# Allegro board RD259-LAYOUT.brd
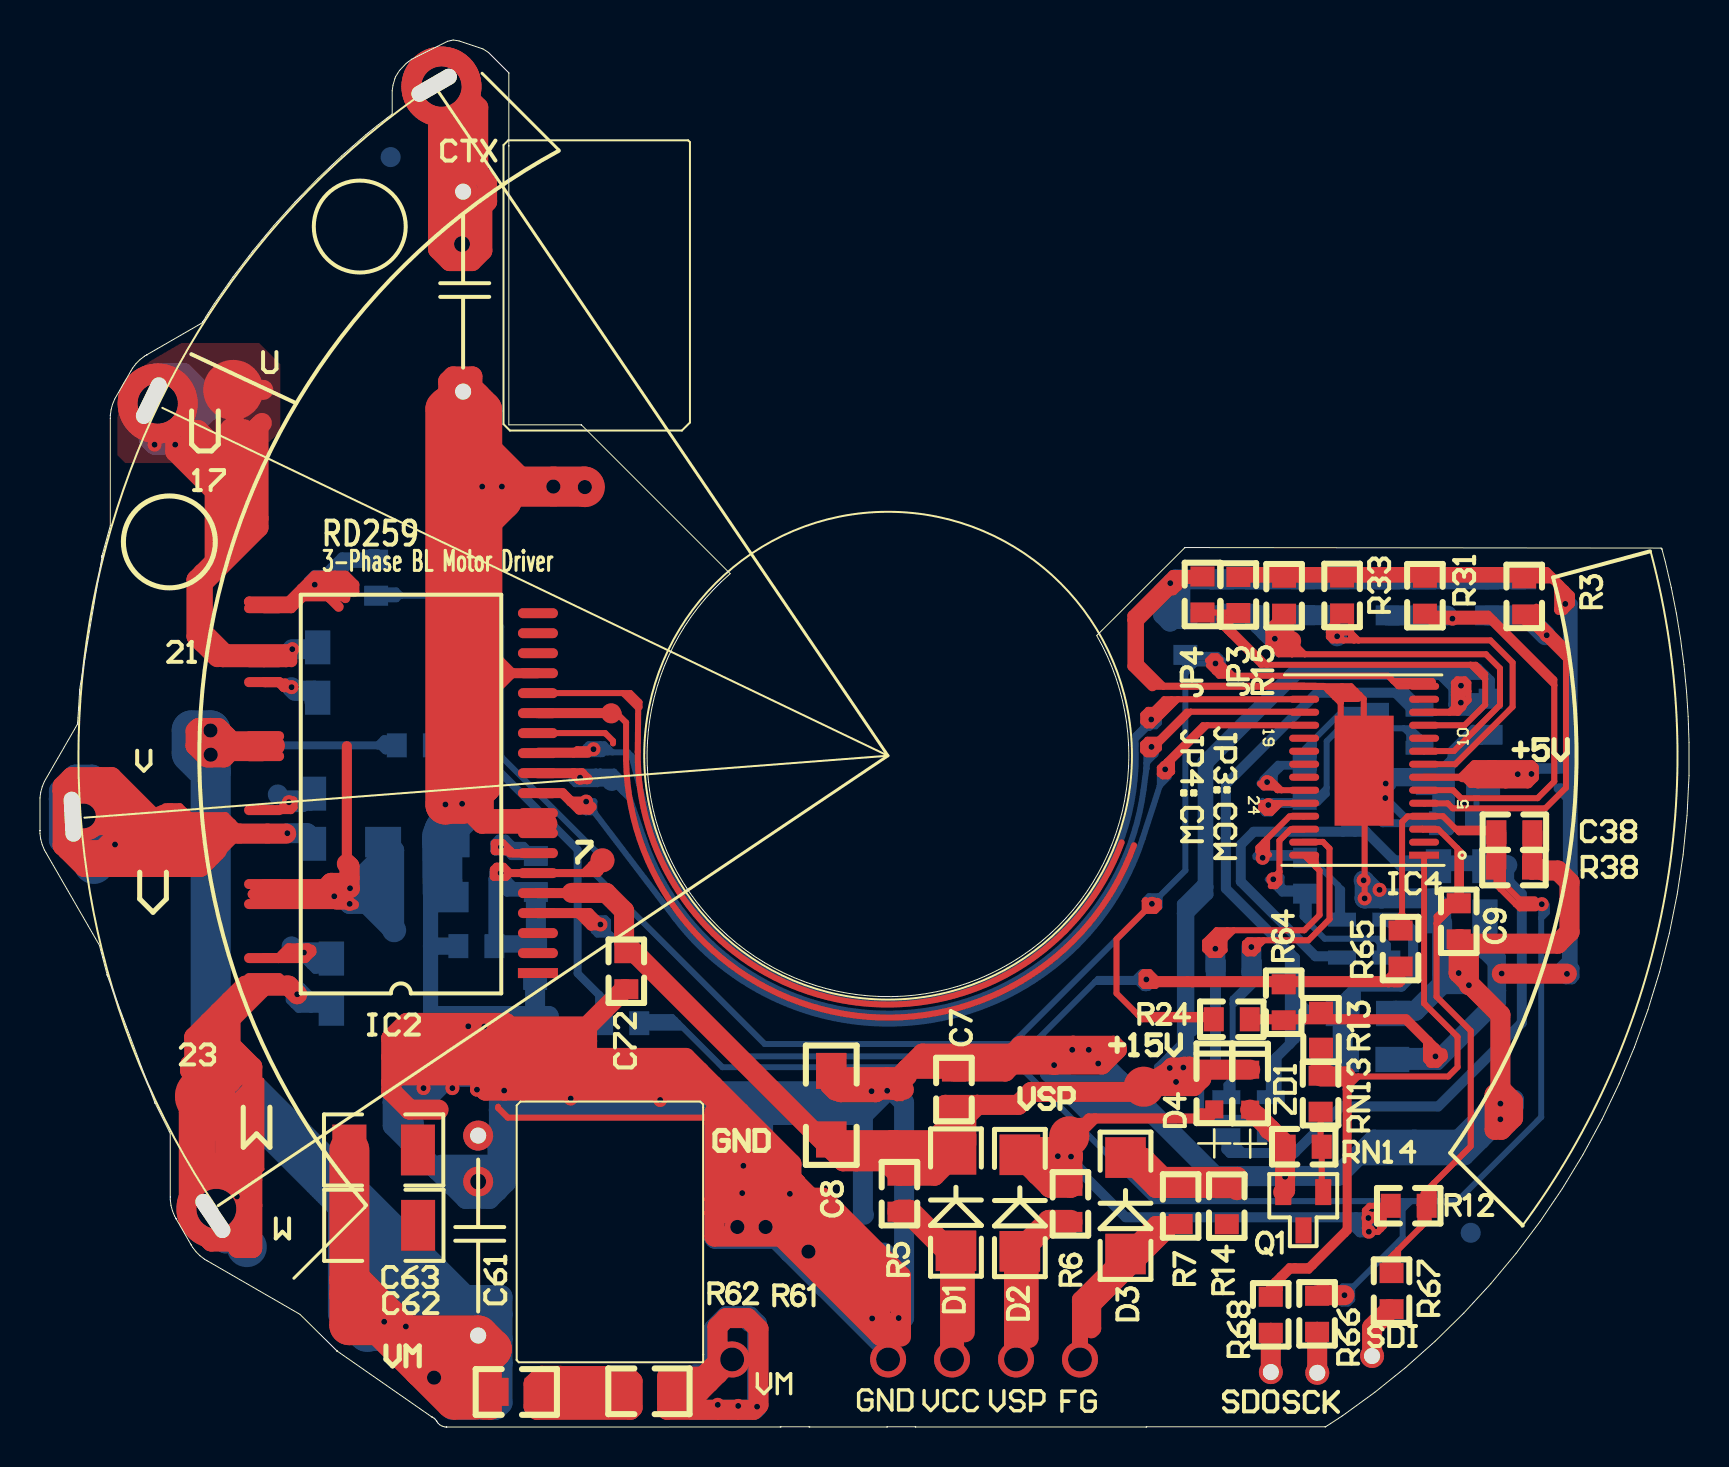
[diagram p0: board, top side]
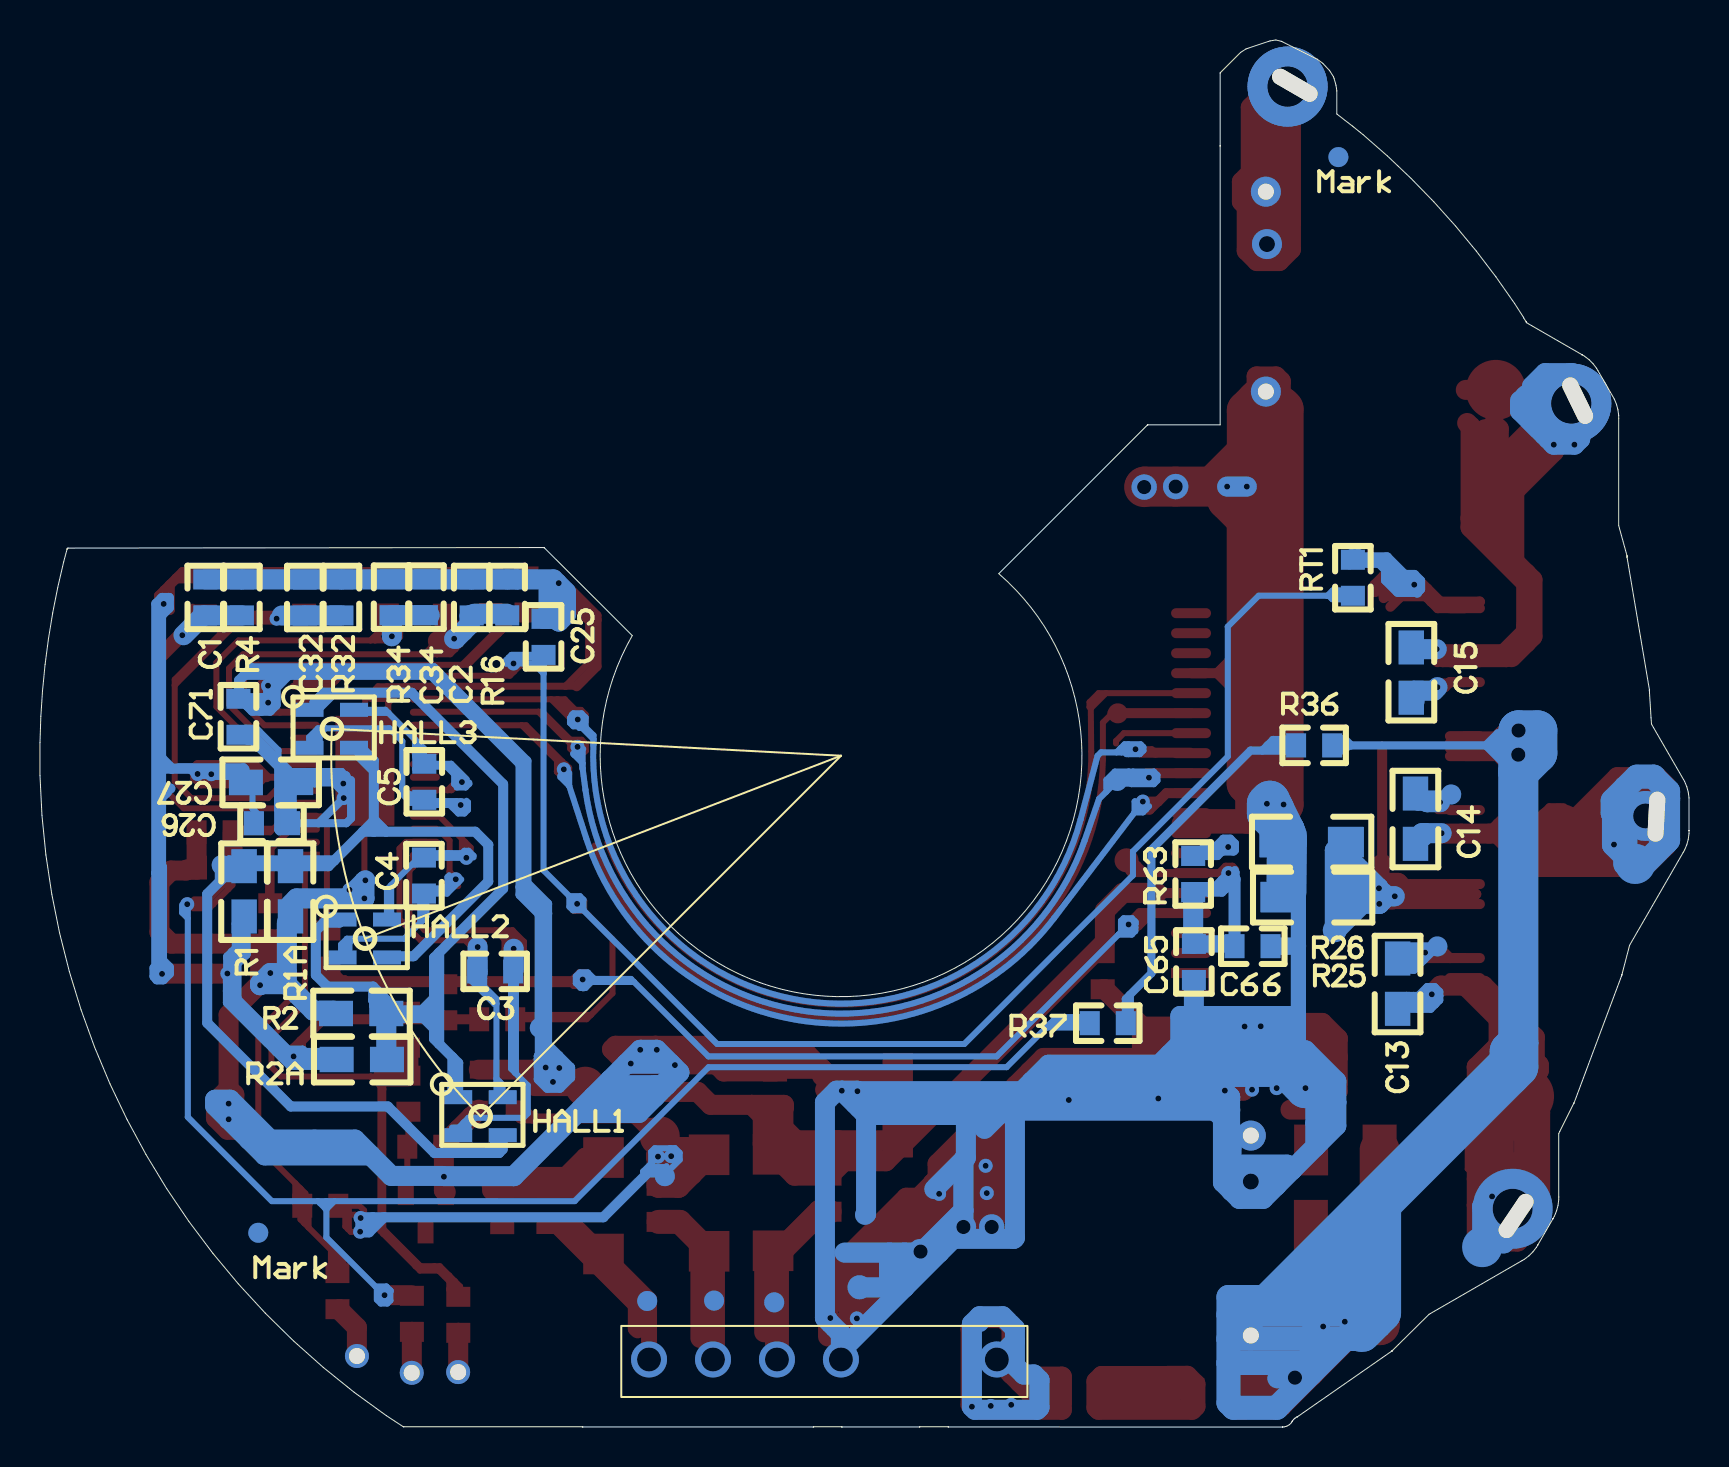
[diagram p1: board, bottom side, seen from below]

Outline 82.5 x 69.38 mm; copper layers: TOP, BOTTOM. Coordinates in mm from the lower left corner of the outline.
Outline path: 0,29.83 0,29.83 0,31.47 0.04,31.75 0.11,32.03 0.22,32.29 1.88,35.16 1.9,35.48 1.98,36.84 1.98,36.85 1.98,36.86 1.98,36.87 3.1,43.5 3.1,43.52 3.1,43.53 3.1,43.54 3.1,43.56 3.1,43.58 3.1,43.58 3.52,45.09 3.52,50.45 3.52,50.6 3.56,50.88 3.63,51.15 3.74,51.42 4.56,52.84 4.63,52.96 4.8,53.19 5,53.39 5.22,53.56 5.34,53.63 5.35,53.64 8.11,55.23 8.14,55.27 8.14,55.28 8.15,55.29 8.27,55.48 8.28,55.49 8.28,55.5 8.28,55.51 8.73,56.2 9.66,57.53 10.65,58.82 11.68,60.08 12.77,61.29 13.9,62.45 15.08,63.57 16.31,64.64 16.83,65.07 17.62,65.68 17.62,66.84 17.66,67.11 17.75,67.44 17.78,67.53 17.99,67.85 18.32,68.21 18.6,68.42 20.39,69.31 20.67,69.38 20.96,69.33 22.16,68.93 22.44,68.75 23.44,67.75 23.44,67.74 23.45,67.74 23.45,67.73 23.46,67.72 23.46,64.08 23.46,64.08 23.46,50.13 27.07,50.13 27.08,50.13 27.09,50.12 27.1,50.11 34.53,42.68 arc(40.41,21.7) 52.87,39.59 57.27,43.98 57.27,43.98 57.28,43.99 57.29,43.99 81.09,43.96 81.1,43.96 81.12,43.95 81.13,43.94 81.13,43.93 81.14,43.91 81.14,43.91 81.31,43.27 81.61,42 81.86,40.72 82.07,39.43 82.24,38.14 82.37,36.84 82.45,35.53 82.5,34.23 82.5,32.58 82.4,30.6 82.2,28.62 81.91,26.65 81.51,24.7 81.03,22.77 80.44,20.87 79.77,19 79,17.17 78.14,15.37 77.19,13.63 76.16,11.93 75.04,10.28 73.85,8.69 72.57,7.16 71.23,5.7 69.81,4.3 68.32,2.98 66.78,1.74 65.17,0.57 64.33,0.02 64.32,0.02 64.31,0.01 64.3,0.01 64.29,0.01 55.37,0.01 55.36,0 55.35,0 55.34,0 43.82,0 43.81,0 43.8,0.01 43.78,0.01 42.4,0.01 42.38,0 42.37,0 42.36,0 38.51,0 38.5,0 38.49,0 38.47,0.01 37.07,0.01 37.06,0 37.05,0 37.04,0 20.34,0 20.33,0 20.26,0 20.12,0.04 20,0.11 19.89,0.21 19.85,0.28 19.85,0.3 19.82,0.33 19.77,0.39 19.71,0.44 19.64,0.49 19.61,0.51 19.6,0.51 19.58,0.52 14.87,3.79 14.85,3.81 14.84,3.82 14.83,3.83 13,5.64 8.36,8.32 8.23,8.39 8.01,8.56 7.81,8.76 7.63,8.99 7.56,9.11 7.56,9.12 6.81,10.42 6.8,10.43 6.73,10.55 6.63,10.81 6.55,11.08 6.52,11.36 6.52,11.51 6.52,14.67 6.47,14.78 5.76,16.19 5.76,16.2 5.75,16.22 3.39,22.54 3.38,22.55 3.37,22.57 3.36,22.6 3.36,22.62 3.36,22.63 2.97,24.09 0.29,28.74 0.22,28.86 0.11,29.13 0.04,29.4 0,29.68 0,29.83

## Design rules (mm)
constraint set DEFAULT: 

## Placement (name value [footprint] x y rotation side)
C1  -  [0603_1]  74.23 42.4 270 bottom
C2  -  [0603_1]  60.9 42.4 270 bottom
C3  -  [0603_1]  60.63 22.79 180 bottom
C4  -  [0603_1]  63.29 28.48 270 bottom
C5  -  [0603_1]  63.27 33.17 270 bottom
C7  -  [0603_1]  45.72 15.98 90 top
C8  -  [1206_1]  39.83 14.39 90 top
C9  -  [0603_1]  70.98 26.2 270 top
C13  -  [0805_1]  14.58 20.92 90 bottom
C14  -  [0805_1]  13.68 29.17 90 bottom
C15  -  [0805_1]  13.89 38.99 270 bottom
C25  -  [0603_1]  57.3 40.42 270 bottom
C26  -  [0603_1]  71.79 30.2 180 bottom
C27  -  [0805_1]  72.19 32.24 180 bottom
C32  -  [0603_1]  69.25 42.39 270 bottom
C34  -  [0603_1]  63.19 42.41 270 bottom
C38  -  [0603_1]  74.66 29.75 180 top
C61  -  [C_CBB]  21.92 4.58 90 top
C62  -  [1210]  15.49 10.09 0 top
C63  -  [1210]  15.48 13.86 0 top
C65  -  [0603_1]  24.77 24.16 270 bottom
C66  -  [0603_1]  22.74 24.05 180 bottom
C71  -  [0603_1]  72.57 36.43 270 bottom
C72  -  [0603_1]  29.33 23.7 270 top
CTX  -  [C_CBB]  21.17 51.79 90 top
D1  -  [RS1M_SMD]  45.81 8.8 90 top
D2  -  [RS1M_SMD]  49.01 8.78 90 top
D3  -  [RS1M_SMD]  54.3 8.64 90 top
D4  -  [D0603]  58.75 15.89 90 top
HALL1  -  [HW101_A]  60.19 15.69 180 bottom
HALL2  -  [HW101_A]  65.97 24.57 180 bottom
HALL3  -  [HW101_A]  67.63 35.06 180 bottom
IC2  -  [SSOP30_TPD4204F]  24.91 22.71 180 top
IC4  -  [TC78B043FNG]  69.24 28.6 180 top
JP3  -  [0603_1]  59.95 42.52 270 top
JP4  -  [0603_1]  58.16 42.54 270 top
NOREF  -  []  6.49 44.22 0 top
NOREF#2  -  []  15.92 60.08 0 top
NOREF#3  -  []  77.04 19.24 0 top
NOREF#4  -  []  57.93 3.08 0 top
NOREF#5  -  []  28.52 9.23 90 top
NOREF#6  -  []  79.56 38.47 0 top
Q1  -  [SOT23_NPN]  63.08 9.79 180 top
R1  -  [0805_1]  72.28 25.54 90 bottom
R1A  -  [0805_1]  69.96 25.54 90 bottom
R2  -  [0805_1]  65.17 20.69 0 bottom
R2A  -  [0805_1]  65.14 18.38 0 bottom
R3  -  [0603_1]  74.25 42.45 270 top
R4  -  [0603_1]  72.4 42.4 270 bottom
R5  -  [0603_1]  43 10.77 90 top
R6  -  [0603_1]  51.55 10.26 90 top
R7  -  [0603_1]  57.06 10.15 90 top
R12  -  [0603_1]  67.57 11.07 0 top
R13  -  [0603_1]  64.09 20.77 270 top
R14  -  [0603_1]  59.37 11.95 270 top
R15  -  [0603_1]  62.24 40.68 90 top
R16  -  [0603_1]  59.12 42.4 270 bottom
R24  -  [0603_1]  58.72 20.39 0 top
R25  -  [1206_1]  20.53 26.26 180 bottom
R26  -  [1206_1]  20.59 29.01 180 bottom
R31  -  [0603_1]  69.28 42.48 270 top
R32  -  [0603_1]  67.42 42.4 270 bottom
R33  -  [0603_1]  65.14 40.69 90 top
R34  -  [0603_1]  64.91 42.41 270 bottom
R36  -  [0603_1]  17.85 34.09 0 bottom
R37  -  [0603_1]  28.18 20.2 0 bottom
R38  -  [0603_1]  74.64 27.98 180 top
R61  -  [0805_2]  31.48 1.79 180 top
R62  -  [0805_2]  24.84 1.76 180 top
R63  -  [0603_1]  24.81 28.56 270 bottom
R64  -  [0603_1]  62.22 20.34 90 top
R65  -  [0603_1]  68.07 24.83 270 top
R66  -  [0603_1]  63.89 6.56 270 top
R67  -  [0603_1]  67.62 7.7 270 top
R68  -  [0603_1]  61.57 6.51 270 top
RN13  -  [0603_1]  64.06 17.57 270 top
RN14  -  [0603_1]  64.12 14.02 180 top
RT1  -  [0603_1]  16.82 41.58 90 bottom
SCK  -  [PAD_FOR_BLDC_S50_1_2_3]  63.9 2.71 0 top
SDI  -  [PAD_FOR_BLDC_S50_1_2_3]  66.64 3.55 0 top
SDO  -  [PAD_FOR_BLDC_S50_1_2_3]  61.58 2.75 0 top
U  -  [PAD_FOR_BLDC_S50_1_2_U]  5.82 51.54 154 top
V  -  [PAD_FOR_BLDC_S50_V]  1.55 31.1 183 top
W  -  [PAD_FOR_BLDC_S50_1_W]  8.24 10.51 214 top
X  -  [PAD_FOR_BLDC_S50_1_2_3_4_X]  19.72 67.11 120 top
ZD1  -  [D0603]  60.54 15.87 90 top

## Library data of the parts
C1 C2 C26 C32 C34 C38 = CC0603KRX7R7BB104
C3-C5 = CC0603KRX7R7BB103
C7 C9 C71 C72 = CC0603KRX7R9BB104
C8 = CL31B106KAHNNNE
C13-C15 = C2012X7R1E225K125AB
C25 = KGM15AR71H102KT
C27 = CC0805KKX7R7BB105
C61 = C4CAWUC3100AA0J
C62 = C3225SMD
C63 = C3225X7T2J104K160AC
C65 = C1608X5R1E105K080AC
C66 = CC0603KRX7R8BB102
CTX = B32529C6102J289
D1-D3 = RS1M
D4 = 1N4148
HALL1-HALL3 = HW101-A
IC2 = TPD4204F
IC4 = TC78B043FNG
JP3 JP4 = RC0603JR-070RL
Q1 = RN1404
R1 R2 = RR1220P-221-D
R1A R2A = R2012SMD
R3 R31 = RC0603FR-074K7L
R4 = RC0603FR-072K2L
R5-R7 = AF0603FR-070RL
R12 = RC0603FR-071KL
R13 R33 R65 RN14 = R1608SMD
R14 = RC0603FR-13100RL
R15 = RC0603FR-0720KL
R16 R32 R34 = RC0603FR-075K1L
R24 = RC0603FR-10220KL
R25 R26 = R3216SMD
R36 R37 = RC0603FR-071ML
R38 = RC0603FR-078K2L
R61 R62 = ESR10EZPJ
R63 R64 = RT0603FRE0710KL
R66-R68 = RC0603FR-1333RL
RN13 = RC0603FR-1010KL
RT1 = PRF18BD471QB5RB
SCK SDI SDO = PAD_FOR_BLDC_S50_S
U = PAD_FOR_BLDC_S50_U
V = PAD_FOR_BLDC_S50_V
W = PAD_FOR_BLDC_S50_W
X = PAD_FOR_BLDC_S50_X
ZD1 = CEZ18V

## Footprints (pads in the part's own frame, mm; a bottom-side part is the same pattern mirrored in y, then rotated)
0603_1
  rect 1x1.2 smd: 1(0,0) 2(1.803,0)
0805_1
  rect 1.7x1.27 smd: 1(0,0) 2(2.515,0)
0805_2
  rect 1.2x1.4 smd: 1(0,0) 2(2,0)
1206_1
  rect 1.8x1.524 smd: 1(-0.008,0.248) 2(3.421,0.248)
1210
  rect 1.7x2.54 smd: 1(0,0) 2(3.429,0)
C_CBB
  round 1.5 hole 0.8: 1(0,0) 2(10,0)
D0603
  rect 0.9x0.9 smd: 1(0,0) 2(2,0)
HW101_A
  rect 1.4x0.7 smd: 1(-1.387,0.809) 2(-1.387,-1.091) 3(0.838,-1.091) 4(0.838,0.809)
PAD_FOR_BLDC_S50_1_2_3
  round 1.2 hole 0.8: 1(0,0)
PAD_FOR_BLDC_S50_1_2_3_4_X
  oval 0.8x2.5 hole 0.8x2.5: 1(0,0)
PAD_FOR_BLDC_S50_1_2_U
  oval 0.8x2.8 hole 0.8x2.5: 1(0.133,0.295)
PAD_FOR_BLDC_S50_1_W
  oval 0.8x2.8 hole 0.8x2.5: 1(-0.363,0.187)
PAD_FOR_BLDC_S50_V
  oval 0.8x2.8 hole 0.8x2.5: 1(-0.053,0.577)
RS1M_SMD
  rect 2.032x2.032 smd: 1(0.012,-0.009) 2(4.838,-0.009)
SOT23_NPN
  rect 0.8x1.3 smd: 1(-1.112,-1.964) 2(-0.123,-0.05) 3(0.888,-1.964)
SSOP30_TPD4204F
  rect 2x0.5 smd: 1(0,0)
  oval 2x0.5 smd: 2(0,-1) 3(0,-2) 4(0,-3) 5(0,-4) 6(0,-5) 7(0,-6) 8(0,-7) 9(0,-8) 10(0,-9) 11(0,-10) 12(0,-11) 13(0,-12) 14(0,-13) 15(0,-14) 16(0,-15) 17(0,-16) 18(0,-17) 19(0,-18) 20(13.7,-18.25) 21(13.7,-15.55) 22(13.7,-14.55) 23(13.7,-11.85) 24(13.7,-10.85) 25(13.7,-8.15) 26(13.7,-7.15) 27(13.7,-4.45) 28(13.7,-3.45) 29(13.7,-0.75) 30(13.7,0.25)
TC78B043FNG
  rect 2.95x5.5 smd: 0(3,-4.225)
  rect 1.5x0.35 smd: 1(0,0)
  oval 1.5x0.35 smd: 2(0,-0.65) 3(0,-1.3) 4(0,-1.95) 5(0,-2.6) 6(0,-3.25) 7(0,-3.9) 8(0,-4.55) 9(0,-5.2) 10(0,-5.85) 11(0,-6.5) 12(0,-7.15) 13(0,-7.8) 14(0,-8.45) 15(6,-8.45) 16(6,-7.8) 17(6,-7.15) 18(6,-6.5) 19(6,-5.85) 20(6,-5.2) 21(6,-4.55) 22(6,-3.9) 23(6,-3.25) 24(6,-2.6) 25(6,-1.95) 26(6,-1.3) 27(6,-0.65) 28(6,0)

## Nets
+7V: C65.1 C66.1 IC2.6 R63.2
GND: C1.1 C2.1 C7.2 C8.2 C9.2 C25.1 C26.2 C27.2 C32.1 C34.1 C38.1 C61.2 C62.2 C63.2 C65.2 C66.2 C71.2 C72.2 CTX.1 IC2.8 IC2.9 IC2.16 IC4.0 IC4.15 JP4.1 Q1.3 R1A.1 R2.2 R4.1 R16.1 R25.1 R26.1 R32.1 R34.1 R38.1 RN14.2 ZD1.1
VCC1: C7.1 C8.1 C71.1 C72.1 D1.2 D4.2 IC2.5 IC4.12 R5.2 ZD1.2
VCC+15V: D1.1 R5.1
BSU: C15.2 IC2.22
BSV: C14.2 IC2.25
BSW: C13.2 IC2.29
DIAG: IC2.4 R64.2 R65.2
DIR: IC4.11 JP3.2 JP4.2
FG: D3.1 R7.1
FGC: C1.2 IC4.5 R3.2 R4.2
FGOUT: IC4.1 R13.2 R68.1 RN13.1
HU: IC2.13 IC4.21
HUM: C3.2 HALL1.2 IC4.28
HUP: C3.1 HALL1.4 IC4.27
HV: IC2.14 IC4.20
HVM: C4.2 HALL2.2 IC4.26
HVP: C4.1 HALL2.4 IC4.25
HW: IC2.15 IC4.19
HWM: C5.2 HALL3.2 IC4.24
HWP: C5.1 HALL3.4 IC4.23
IDC: C25.2 IC4.14 R24.1 RT1.1
IS: IC2.20 IC2.27 IC2.28 R25.2 R26.2 RT1.2
LA: C2.2 IC4.9 R15.1 R16.2
LAOFS: C34.2 IC4.8 R33.1 R34.2
LATYPE: C32.2 IC4.6 R31.2 R32.2
LU: IC2.10 IC4.18
LV: IC2.11 IC4.17
LW: IC2.12 IC4.16
NETD2_2: D2.2 D4.1 R6.2 R12.1
NETD3_2: D3.2 R7.2 R14.1
NETHALL1_1: HALL1.1 HALL2.1 HALL3.1 R2.1 R2A.1
NETHALL1_3: HALL1.3 HALL2.3 HALL3.3 R1.2 R1A.2
NETQ1_1: Q1.1 RN13.2 RN14.1
NETQ1_2: Q1.2 R14.2
NETR36_2: R36.2 R37.1
NETR61_2: R61.2 R62.1
RES: C38.2 IC4.4 R37.2 R38.2 R65.1 R66.1
SCK: R66.2 SCK.1
SD: IC2.7 R63.1
SDI: R67.2 SDI.1
SDO: R68.2 SDO.1
TX: CTX.2 X.1
U: C15.1 IC2.21 U.1
V: C14.1 IC2.26 V.1
VM: R61.1
VM+310V: C61.1 C62.1 C63.1 IC2.23 IC2.24 R36.1 R62.2
VREG: C26.1 C27.1 IC4.7 JP3.1 R1.1 R2A.2 R3.1 R13.1 R15.2 R24.2 R31.1 R33.2 R64.1
VSP: D2.1 R6.1
VSP1: C9.1 IC4.3 R12.2 R67.1
W: C13.1 IC2.30 W.1

Pads without a net: IC2 1 2 3 17 18 19; IC4 2 10 13 22

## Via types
v1: diameter 0.7, hole 0.3, TOP to BOTTOM, 92 vias
v2: diameter 1.27, hole 0.711, TOP to BOTTOM, 8 vias
v3: diameter 1.5, hole 0.8, TOP to BOTTOM, 2 vias
v4: diameter 1.8, hole 1.2, TOP to BOTTOM, 5 vias
v5: diameter 4, hole 2, TOP to BOTTOM, 5 vias
v6: diameter 2.5, hole 1.25, TOP to BOTTOM, 1 via

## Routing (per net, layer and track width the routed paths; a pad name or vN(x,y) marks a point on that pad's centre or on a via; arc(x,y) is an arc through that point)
+7V: length 25.4
  TOP w0.4: 27.21,27.71 IC2.6 23.5,27.71 ; 27.21,27.71 27.91,27.71 ; 27.21,27.71 27.6,28.1 ; 27.6,28.1 27.6,28.02 27.91,27.71 ; 27.6,28.1 27.99,28.49 ; 27.91,27.71 27.99,27.79 27.99,28.19 28.14,28.35 ; 23.5,27.71 23.18,28.03 22.85,28.03 22.7,27.88 22.7,27.52 23.31,27.52 23.5,27.71 ; 23.5,27.71 23.05,27.71 v1(23.04,27.71)
  BOTTOM w0.4: 22.72,27.86 22.72,27.77 22.68,27.74 22.68,27.4 23.1,26.99 ; 23.1,27.65 v1(23.04,27.71) 22.96,27.71 ; 23.1,27.65 23.4,27.36 ; 23.1,27.65 23.1,26.99 ; 23.4,27.36 23.69,27.06 ; 23.4,27.36 23.19,27.15 23.19,26.89 ; 23.19,26.89 23.1,26.99 ; 23.19,26.89 23.36,26.73 24.03,26.73 ; 23.19,26.89 23.86,26.89 ; 24.03,26.73 24.77,26.73 R63.2 24.51,27.06 23.69,27.06 ; 24.03,26.73 23.86,26.89 ; 23.69,27.06 23.86,26.89
  BOTTOM w0.6: v1(23.04,27.71) 22.74,27.4 C66.1
  BOTTOM w0.864: C66.1 22.85,24.16 C65.1
  BOTTOM w1: R63.2 24.81,24.16
GND: length 771.8
  TOP w0.3: 63.25,37.04 IC4.15 65.13,37.05 ; 22.92,16.02 22.92,15.96 23.4,15.48 33.45,15.48 33.75,15.18 ; 65.82,36.82 65.58,37.05 65.13,37.05 ; 65.82,36.82 66.02,36.62 ; 65.82,36.82 65.07,36.82 ; 66.02,36.62 65.92,36.52 ; 66.02,36.62 66.22,36.41 66.22,32.85 ; 65.13,37.05 65.07,36.99 65.07,36.82 ; 65.07,36.52 65.07,36.82 ; 65.07,36.52 64.77,36.52 ; 65.07,36.52 65.07,36.21 ; 65.07,36.82 64.47,36.82 ; 65.07,36.21 65.07,34 66.22,32.85 ; 65.07,36.21 64.77,36.52 ; 64.77,36.52 64.47,36.82 ; 64.24,37.04 64.47,36.82 ; 42.69,16.87 42.69,16.62 42.86,16.45 43.11,16.45 ; 45.62,17.78 C7.2 ; JP4.1 58.08,42.62 ; 66.22,32.85 IC4.0 66.27,32.8 v1(66.27,26.44)
  TOP w0.35: 56.89,42.62 56.89,42.05 56.69,41.84 56.63,41.84 55.05,40.26 55.05,38.21 56.21,37.05 ; 55.65,37.05 56.21,37.05 ; 56.21,37.05 IC4.15 ; 63.25,37.04 64.24,37.04
  TOP w0.4: 21.15,31.14 21.19,31.14 ; 21.19,31.14 22.07,31.14 22.5,30.71 ; 21.19,31.14 21.16,31.17 v1(21.12,31.17) ; 21.19,31.14 21.63,30.71 22.5,30.71 ; 22.5,30.71 22.5,31.81 22.13,32.19 ; 22.5,30.71 IC2.9 ; 22.29,37.71 22.13,37.55
  TOP w0.5: v1(56.54,42.21) 56.6,42.21 56.81,42.42 57.26,42.42 ; 56.68,41.84 56.89,42.05 57.26,42.42 ; 56.89,42.62 56.68,42.62 54.65,40.59 54.65,40.38 ; 56.89,42.62 58.08,42.62 ; 56.89,42.62 56.75,42.47 ; 22.13,36.27 22.17,36.27 23.6,37.71 ; 23.6,37.71 22.6,38.71 22.13,38.71 ; 23.6,37.71 IC2.16 ; 23.6,37.71 22.29,37.71 ; 58.09,42.47 JP4.1 ; 58.09,42.47 57.31,42.47 ; 58.09,42.47 58.03,42.42 57.26,42.42 ; 57.31,42.47 57.26,42.42 ; 57.31,42.47 56.75,42.47 ; 55.65,37.05 54.65,38.05 54.65,40.38 ; 65.07,36.52 65.92,36.52 ; 56.75,42.47 54.65,40.38
  TOP w1: 27.18,18.46 32.29,18.46 32.98,17.77 ; 27.18,18.46 23.89,18.46 ; 27.18,18.46 27.37,18.65 27.37,19.31 ; 37.82,12.18 37.82,11.47 ; 37.82,12.18 37.82,12.2 37.59,12.43 ; 37.82,12.18 38.53,11.47 ; 37.82,12.18 37.59,12.41 37.59,12.43 ; 37.82,11.47 42.53,6.76 43.07,6.76 ; 37.82,11.47 38.53,11.47 ; 37.82,11.47 37.69,11.47 ; 35.02,15.74 37.59,13.16 37.59,12.43 ; 35.02,15.74 33.67,17.09 ; 35.02,15.74 34.52,15.74 ; 73.06,16.92 73.69,16.28 73.69,15.46 73.11,14.87 72.77,14.87 72.77,16.63 73.06,16.92 ; 73.06,16.92 73.06,20.62 71.49,22.19 ; 73.06,16.92 v1(73.06,16.18) 73.06,16.17 v1(73.06,15.39) ; 17.57,17.24 17.57,16.8 18.5,15.87 19.94,15.87 ; 17.57,17.24 17.92,17.59 23.39,17.59 23.89,17.09 ; 17.57,17.24 17.57,18.5 ; 71.49,22.19 v1(70.97,22.71) 70.98,22.71 C9.2 71.08,24.39 71.29,24.18 ; 71.49,22.19 71.49,23.98 71.29,24.18 ; 71.49,22.19 v1(71.49,22.1) ; 24.15,16.83 33.28,16.83 34.37,15.74 ; 24.15,16.83 23.89,17.09 ; 24.15,16.83 v1(23.22,16.83) 22.29,16.83 22.03,17.09 23.89,17.09 ; 61.57,14.87 60.9,15.53 60.88,15.53 ZD1.1 ; 61.57,14.87 61.48,14.87 ; 61.57,14.87 62.32,14.12 RN14.2 ; 34.71,12.84 36.07,11.47 ; 34.71,12.84 34.71,11.47 ; 34.71,12.84 34.71,12.95 ; 34.71,12.84 34.65,12.89 34.71,12.95 ; 36.07,11.47 34.71,11.47 ; 36.07,11.47 36.78,11.47 ; 20.42,51.05 20.42,52.31 20.66,52.55 21.63,52.55 21.63,51.23 21.19,50.79 ; 51.7,19.07 49.07,19.07 48.67,18.68 44.15,18.68 43.38,17.92 ; 51.7,19.07 50.76,18.13 ; 51.7,19.07 53.7,19.07 53.88,18.89 53.12,18.13 50.76,18.13 ; 27.37,19.31 27.37,20.03 ; 27.37,19.31 27.25,19.43 23.89,19.43 ; 27.37,20.03 23.48,20.03 ; 27.37,20.03 29.23,21.9 C72.2 ; 23.89,17.09 23.89,17.77 ; 23.89,17.09 33.67,17.09 ; 23.89,17.77 32.98,17.77 ; 23.89,17.77 23.89,18.03 ; 23.89,17.77 22.79,17.77 22.54,18.03 ; 34.71,12.95 35.27,13.51 35.27,13.89 37.69,11.47 ; 34.71,12.95 34.71,14.34 35.15,14.78 35.15,14.87 37.59,12.43 ; 33.67,17.09 32.98,17.77 ; 38.53,11.47 39.15,11.47 43.07,7.55 43.07,6.76 ; 42.43,4.57 42.43,5.14 37.56,10.01 v2(34.89,10.01) ; 42.43,4.57 42.03,4.57 37.07,9.53 33.75,9.53 33.75,10.7 ; 42.43,4.57 v4(42.43,3.38) ; 20.4,51.03 21.19,50.24 ; 21.19,50.24 21.19,50.79 ; 21.19,50.24 21.19,47.97 ; 42.69,16.87 43.37,17.56 ; 42.69,16.87 41.94,16.87 ; 42.69,16.87 43.22,16.87 ; C7.2 48.29,17.78 48.64,18.13 50.76,18.13 ; 21.19,50.79 21.19,51.79 ; 43.07,6.76 43.07,4.53 ; 23.89,18.03 22.54,18.03 ; 23.89,18.03 23.89,18.46 ; 22.54,18.03 18.21,18.03 17.74,18.5 ; 37.69,11.47 36.78,11.47 ; 33.75,10.7 37.29,10.7 41.7,6.29 ; 33.75,10.7 33.75,11.39 ; 43.38,17.92 42.96,17.5 42.39,17.5 ; 43.38,17.92 45.28,17.92 45.38,18.02 ; 42.39,17.5 39.79,17.5 39.53,17.23 39.53,17.09 39.79,16.83 39.97,16.83 40.05,16.75 41.82,16.75 41.94,16.87 ; 42.39,17.5 42.39,17.32 41.94,16.87 ; 17.74,18.5 17.57,18.5 ; 17.74,18.5 17.83,18.59 22.7,18.59 ; 17.57,18.5 17.57,19.43 ; 33.75,11.39 33.82,11.47 34.71,11.47 ; 33.75,11.39 33.75,15.74 34.37,15.74 ; 71.29,24.18 75.93,24.18 76.52,24.76 76.52,27.25 75.93,27.84 75.18,27.84 75.13,27.88 74.64,27.88 R38.1 74.64,28.08 74.66,28.1 C38.1 ; 23.89,18.46 23.89,18.59 ; 23.89,18.46 22.83,18.46 22.7,18.59 ; 23.89,18.59 23.89,19.43 ; 23.89,18.59 22.7,18.59 ; 23.89,19.43 23.89,19.63 23.48,20.03 ; 23.89,19.43 23.3,19.43 ; 41.94,16.87 41.68,16.87 v1(41.6,16.8) ; 23.48,20.03 23.31,20.21 18.35,20.21 17.57,19.43 ; 23.48,20.03 v1(22.23,20.03) ; 34.37,15.74 34.52,15.74 ; 50.76,18.13 v1(50.73,18.1) ; 25.38,30.18 22.11,30.18 v1(21.12,31.17) ; Q1.3 62.29,11.84 v1(62.29,12.52) 62.29,14.07 ; 17.57,19.43 23.3,19.43 ; 34.71,11.47 34.52,11.66 34.52,15.74 ; 23.31,19.42 23.3,19.43 ; 36.78,11.47 v1(35.19,13.07) ; 21.19,47.97 v1(22.12,47.04) 21.48,47.04 21.19,47.33 21.19,47.97
  TOP w2: v2(27.26,47.01) 27.23,47.04 v2(25.68,47.04) 23.82,47.04 ; 23.82,47.04 22.12,48.74 ; 23.82,47.04 v1(23.11,47.04) ; 22.12,48.74 v1(22.12,47.04) ; 22.12,48.74 22.12,50.84 CTX.1 ; v1(23.11,47.04) v1(22.12,47.04) ; v1(23.11,47.04) 23.11,46.39 22.13,45.41 ; 22.13,45.41 22.13,47.03 v1(22.12,47.04) ; 22.13,45.41 22.13,32.19 v1(21.12,31.17) 20.32,31.17 v1(20.28,31.14) 20.28,50.91 20.42,51.05
  BOTTOM w0.3: 72.38,34.81 72.22,34.97 71.68,34.97 70.56,33.86 70.56,33.45 ; 72.38,34.81 C71.2 ; 72.38,34.81 71.93,34.81 70.56,33.45 ; 70.63,31.18 70.63,31.34 ; 70.63,31.18 70.1,31.18 69.99,31.07 ; 70.63,31.18 70.63,30.88 ; 70.63,31.34 70.63,31.5 ; 70.63,31.34 70.04,31.34 69.99,31.28 ; C71.2 72.32,34.38 72.2,34.38 ; C71.2 72.2,34.62 ; 69.84,32.24 69.89,32.24 70.63,32.98 ; 69.84,32.24 C27.2 69.99,31.93 69.99,31.5 ; 69.84,32.24 70.33,32.73 70.33,32.92 ; 58.44,42.21 58.62,42.4 ; 66.93,32.36 67.39,32.81 69.93,32.81 70.56,33.45 ; 70.63,30.88 70.63,29.87 70.57,29.81 70.57,29.78 70.53,29.74 ; 70.63,30.88 70.18,30.88 69.99,31.07 ; 70.63,31.5 69.99,31.5 69.99,31.5 ; 70.63,31.5 70.63,32.98 ; 69.99,31.07 69.99,31.28 ; 69.99,31.07 C26.2 ; 69.99,31.28 69.99,31.5 ; 70.63,32.98 71.93,34.27 ; 71.93,34.27 71.68,34.27 70.33,32.92 ; 71.93,34.27 72.12,34.27 72.2,34.36 72.2,34.38 ; 72.2,34.38 72.2,34.62 ; 72.2,34.38 71.59,34.38 ; 70.33,32.92 70.33,33.11 70.56,33.35 ; 68.77,32.18 68.98,32.18 69.07,32.28 69.07,32.49 69.29,32.49 69.53,32.24 69.8,31.98 69.8,30.67 ; 57.3,42.16 57.26,42.21 ; 72.2,34.62 71.84,34.62 71.59,34.38 ; 70.56,33.45 70.56,33.35 ; 56.87,40.33 56.97,40.33 ; 70.56,33.35 71.59,34.38
  BOTTOM w0.4: 67.32,31.75 v1(67.32,32.18) ; 67.32,31.75 67.32,31.48 v1(67.3,31.46) 68.56,30.2 ; 67.32,31.75 67.63,32.05 ; C27.2 68.82,32.24 ; 68.56,30.2 C26.2 ; 68.56,30.2 67.17,30.2 66.93,30.44 66.93,32.36 ; 67.2,32.59 67.17,32.59 ; 67.2,32.59 69.03,32.59 69.07,32.55 69.07,32.49 68.82,32.24 ; 67.2,32.59 67.2,32.33 67.29,32.24 ; 68.82,32.24 67.26,32.24 ; 68.82,32.24 68.77,32.18
  BOTTOM w0.5: 53.13,15.71 52.77,16.07 ; 52.77,16.07 52.33,16.51 51.73,17.1 50.8,18.03 v1(50.73,18.1) ; 52.77,16.07 55.47,16.07 55.47,15.71 ; v1(62.29,12.52) 62.26,12.55 ; 68.98,14.6 68.76,14.38 ; v1(56.54,42.21) 58.44,42.21 ; C25.1 57.3,42.16
  BOTTOM w0.762: R25.1 19.54,26.51 19.54,18.85
  BOTTOM w0.864: C66.2 19.59,24.05
  BOTTOM w1: 72.04,14.38 v1(73.06,15.39) 73.06,15.39 ; 72.04,14.38 71.25,13.59 65.95,13.59 ; 72.04,14.38 70.99,14.38 ; 56.63,42.21 56.63,41.1 57.2,40.52 57.2,40.42 ; 56.63,42.21 56.82,42.4 R16.1 C2.1 R32.1 R4.1 C1.1 ; 56.63,42.21 56.18,41.76 56.18,40.64 56.53,40.29 56.67,40.42 57.2,40.42 ; 17.65,16.24 17.65,17.3 19.18,18.84 20.22,18.84 20.42,18.65 25.97,18.65 ; 17.65,16.24 18.69,15.19 ; 17.65,16.24 17.87,16.24 18.88,17.25 ; 17.65,16.24 17.65,15.07 18.69,14.03 ; 67.12,26.44 66.27,27.3 ; 67.12,26.44 v1(66.27,26.44) 66.27,27.3 ; 67.12,26.44 69.66,26.44 69.96,26.14 ; 66.27,27.3 v1(66.22,27.34) ; 70.15,22.15 68.82,20.82 67.82,20.82 R2.2 ; 70.15,22.15 70.15,22.73 ; 70.15,22.15 71.44,22.15 v1(71.49,22.1) 71.49,22.19 v1(70.97,22.71) 70.17,22.71 70.15,22.73 ; 22.89,13.12 22.89,14 22.93,14.04 22.96,14.04 ; 22.89,13.12 20.11,13.12 19.85,12.86 ; 22.89,13.12 22.96,13.12 22.96,14.04 ; 22.89,13.12 22.89,11.8 ; 40,8.72 39.25,8.72 ; 40,8.72 42.24,8.72 ; 40,8.72 40.02,8.7 40.02,6.98 ; 39.25,8.72 37.51,8.72 ; 39.25,8.72 39.25,6.98 ; 36.3,13.35 36.18,13.48 36.18,15.61 ; 36.3,13.35 37.75,11.9 ; 36.3,13.35 36.3,10.84 ; v1(42.38,16.82) 41.63,16.82 v1(41.6,16.8) ; v1(42.38,16.82) 41.17,15.61 ; v1(42.38,16.82) 42.64,16.82 43.23,16.24 43.23,5.46 42.43,4.66 42.43,3.8 ; 51.14,17.1 50.51,17.74 50.95,18.18 ; 51.14,17.1 53.72,17.1 53.98,17.36 ; 51.14,17.1 51.74,16.51 ; 18.69,15.19 18.69,14.03 ; 18.69,15.19 18.69,16.95 ; 24.77,20.56 25.45,20.56 25.45,19.17 ; 24.77,20.56 C65.2 ; 24.77,20.56 23.92,20.56 ; 42.43,3.8 39.25,6.98 ; 42.43,3.8 v4(42.43,3.38) ; 22.96,14.04 22.96,15.85 ; 19.85,12.86 18.69,14.03 ; 19.85,12.86 20.65,12.07 ; 19.85,12.86 21.33,12.86 v3(21.92,12.28) ; 62.34,12.56 64.92,12.56 65.95,13.59 ; 70.15,22.73 70.15,25.23 ; 41.17,15.61 40.41,15.61 ; 41.17,15.61 41.17,10.67 41.22,10.61 ; 40.02,6.98 41.2,6.98 ; 40.02,6.98 39.25,6.98 ; 36.18,15.61 34.55,15.61 ; 36.18,15.61 40.41,15.61 ; 37.51,8.72 36.82,9.41 ; 37.51,8.72 39.25,6.98 ; 25.45,19.17 25.97,18.65 ; 25.45,19.17 21.07,19.17 20.21,20.03 20.74,20.56 ; 25.97,18.65 26.5,18.12 32.04,18.12 32.88,17.28 ; 53.98,17.36 53.15,18.18 ; 53.98,17.36 54.8,16.53 ; 50.95,18.18 v1(52.94,18.18) 53.15,18.18 ; 50.95,18.18 v1(51.64,18.87) v1(52.47,18.87) 53.15,18.18 ; 41.04,16.23 v1(41.6,16.8) ; 41.04,16.23 40.41,15.61 ; 41.04,16.23 40.84,16.44 33.72,16.44 ; v1(41.6,16.8) 33.36,16.8 ; 22.96,15.85 22.98,15.83 23.71,15.83 ; 22.96,15.85 22.96,16.51 ; 22.89,11.8 22.49,11.41 21.31,11.41 20.65,12.07 ; 22.89,11.8 22.62,12.07 20.65,12.07 ; 22.89,11.8 23.32,12.23 23.32,15.44 23.71,15.83 ; 33.72,16.44 31.98,16.44 ; 33.72,16.44 33.36,16.8 ; 33.72,16.44 34.55,15.61 ; 33.72,16.44 33.72,15.78 ; 31.98,16.44 23.03,16.44 22.96,16.51 ; 31.98,16.44 32.34,16.8 33.36,16.8 ; 57.2,40.42 C25.1 ; 23.71,15.83 33.67,15.83 33.72,15.78 ; 70.99,14.38 66.74,14.38 65.95,13.59 ; 70.99,14.38 72.98,16.37 73.73,16.37 73.73,16.07 73.06,15.39 ; 73.06,15.39 v1(73.06,16.18) ; 23.92,20.56 20.74,20.56 ; 23.92,20.56 23.4,20.04 ; 20.74,20.56 19.66,20.56 ; 33.36,16.8 32.88,17.28 ; 36.82,9.41 33.78,9.41 33.72,9.47 33.72,15.78 ; 36.82,9.41 36.3,9.93 v2(36.3,10.01) 36.3,10.84 ; 23.4,20.04 24.76,20.04 ; 23.4,20.04 v1(21.43,20.04) ; 32.88,17.28 23.6,17.28 22.87,18.01 ; 22.96,16.51 23.28,16.83 ; 34.55,15.61 35.25,14.91 ; 36.3,10.84 38.4,8.73 ; 54.8,16.53 54.78,16.51 51.74,16.51 ; 54.8,16.53 58.79,12.55 62.26,12.55 ; 51.74,16.51 52.54,15.71 55.47,15.71 ; v1(22.12,47.04) v1(23.11,47.04) ; 19.07,16.95 v1(19.19,16.95)
  BOTTOM w2: 20.22,18.01 20.22,18.84 20.21,20.03 ; 20.22,18.01 v1(19.19,16.95) 19.11,17.02 18.88,17.25 ; 20.22,18.01 25.35,18.01 25.68,17.68 ; 20.22,29.32 20.22,29.8 ; 20.22,29.8 21.12,30.7 v1(21.12,31.17) 20.97,31.32 20.94,31.26 20.76,30.9 20.22,29.8 ; 20.11,29.55 20.12,29.25 20.14,26.77
  vias: v1(20.63,16.95) v1(21.86,16.87) v1(26.55,16.43) v1(31.03,16.36) v1(35.13,11.7) v1(37.52,11.66) v1(41.63,5.43) v1(42.96,5.45) v1(67.01,26.87) v2(38.44,8.77)
VCC1: length 173.5
  TOP w0.3: 71.16,36.67 71.09,36.61 70.73,36.61 ; v1(71.09,37.08) 70.98,37.08 70.82,36.92 70.73,36.92 ; 70.73,36.61 70.73,35.99 ; 70.73,36.61 70.73,36.77 ; 70.73,35.99 70.97,36.23 v1(71.08,36.23) ; 70.73,35.99 70.49,35.75 ; 70.73,36.92 70.73,37.23 70.9,37.4 71.28,37.4 71.46,37.22 71.46,36.79 ; 70.73,36.92 70.73,36.77 ; 70.73,36.77 71.43,36.77 71.46,36.79 ; 71.46,36.79 71.46,36.37 ; 26.6,26.72 26.59,26.71
  TOP w0.35: 70.93,35.75 70.93,35.84 71.19,36.09 ; 70.93,35.75 IC4.12 ; 70.93,35.75 71.19,36.01 71.19,36.09 ; 71.19,36.09 71.19,36.3 71.16,36.33 71.16,37.01 v1(71.09,37.08) ; 71.19,36.09 71.46,36.37
  TOP w0.5: 26.59,26.71 IC2.5
  TOP w1: 55.27,17.05 55.22,17.02 55.25,17.05 55.27,17.05 ; 55.27,17.05 55.72,17.05 ; 55.27,17.05 56.4,17.74 ; 46.89,16.11 45.28,16.11 45.41,15.98 ; 46.89,16.11 46.34,15.56 46.34,14.16 D1.2 ; 46.89,16.11 48.95,16.11 49.59,16.76 55.43,16.76 55.72,17.05 ; 45.43,13.24 44.75,12.57 R5.2 42.28,13.29 ; 45.43,13.24 45.38,13.29 42.28,13.29 ; 45.43,13.24 D1.2 ; 45.31,14.96 45.31,15.95 45.28,15.98 45.41,15.98 ; 45.31,14.96 44.69,14.34 42.83,14.34 ; 45.31,14.96 45.31,14.16 ; 39.53,14.2 39.53,13.94 ; 39.53,13.94 29.22,24.25 29.22,25.82 28.32,26.72 26.6,26.72 ; 39.53,13.94 40.18,13.29 40.83,13.29 ; 45.31,14.16 45.31,13.87 43.31,13.87 42.83,14.34 ; 45.31,14.16 D1.2 ; 40.83,13.29 42.28,13.29 ; 40.83,13.29 40.83,14.34 ; 42.28,13.29 42.57,13.58 42.57,14.34 ; 42.28,13.29 41.65,13.91 ; 42.83,14.34 42.57,14.34 ; 57.54,17.25 57.54,17.61 57.51,17.65 57.51,17.87 ; 45.41,15.98 45.82,15.57 D1.2 ; 45.41,15.98 C7.1 ; 57.51,18.02 57.51,17.87 ; 57.51,18.02 57.66,17.87 ; 57.51,18.02 57.24,18.02 v1(57.2,17.98) 56.65,17.98 55.72,17.05 ; 57.51,17.87 57.66,17.87 ; 57.66,17.87 58.1,17.43 57.72,17.05 55.72,17.05 ; 57.66,17.87 ZD1.2 ; 42.57,14.34 40.83,14.34 ; 39.53,14.34 40.83,14.34 ; v1(56.83,17.26) 57.19,17.61
  BOTTOM w0.3: 72.74,36.6 72.82,36.68 ; 72.74,36.6 72.62,36.73 ; 72.74,36.6 C71.1 72.22,36.08 71.68,36.08 71.43,35.83
  BOTTOM w0.5: 58.46,27.01 58.46,26.63 57.5,25.67 ; 58.46,27.01 58.46,33.16 62.92,37.62 70.06,37.62 ; 58.46,27.01 58.16,26.72 ; 56.79,17.35 56.79,17.3 v1(56.83,17.26) ; 56.79,17.35 56.56,17.59 56.56,17.92 v1(56.52,17.96) 56.52,18.01 56.6,18.09 ; 56.79,17.35 56.83,17.31 ; 56.79,17.35 56.79,17.62 ; 58.16,27.2 58.16,33.31 62.8,37.95 71.93,37.95 72.26,37.62 ; 58.16,27.2 58.16,26.72 ; 58.16,27.2 57.13,26.17 57.13,25.68 ; 57.54,18.02 57.54,17.4 57.11,16.97 56.5,16.97 55.98,17.49 ; 57.54,18.02 57.54,18.38 ; 57.54,18.02 56.87,17.35 ; 56.87,17.35 56.87,17.6 57.2,17.93 v1(57.2,17.98) 57.2,18.04 57.54,18.38 ; 56.87,17.35 56.83,17.31 ; 56.87,17.35 56.87,17.3 v1(56.83,17.26) ; 57.54,18.38 57.54,18.55 57.49,18.6 ; 57.5,25.67 57.5,26.05 ; 57.5,25.67 57.5,19.98 57.49,19.97 57.49,18.6 ; 57.5,26.05 58.16,26.72 ; 57.5,26.05 57.13,25.68 ; 72.5,36.46 72.12,36.08 71.87,35.83 71.43,35.83 ; 72.5,36.46 72.54,36.46 ; 72.5,36.46 71.36,36.46 ; 57.49,18.6 57.2,18.89 ; 57.49,18.6 57.49,18.55 ; 57.2,18.89 57.2,19.06 57.13,19.06 57.13,19.13 ; 57.2,18.89 57.2,18.69 56.6,18.09 ; 70.06,37.62 70.7,36.98 70.7,36.12 71,35.83 71.43,35.83 ; 70.06,37.62 70.55,37.62 ; 56.6,18.09 56.55,18.14 56.55,18.55 ; 56.6,18.09 56.79,17.89 56.79,17.62 ; v1(56.83,17.26) 56.78,17.26 56.55,17.49 ; v1(56.83,17.26) 56.83,17.31 ; 71.43,35.83 71.43,36.39 71.36,36.46 ; 56.79,17.62 56.66,17.49 56.55,17.49 ; 72.54,36.46 72.54,37.34 72.26,37.62 ; 72.54,36.46 C71.1 ; 56.55,18.55 55.98,17.98 ; 56.55,18.55 57.13,19.13 ; 55.98,17.98 56.06,17.98 56.55,17.49 ; 55.98,17.98 55.98,17.49 ; 71.36,36.46 71.14,36.23 v1(71.08,36.23) 71.09,36.23 71.09,37.08 v1(71.09,37.08) 70.55,37.62 ; 56.83,17.31 56.83,17.46 ; 56.55,17.49 55.98,17.49 ; 57.13,19.13 57.13,25.68 ; 70.55,37.62 72.26,37.62
VCC+15V: length 12.9
  TOP w1: 46.27,4.74 46.27,7.98 45.63,8.62
  TOP w1.2: v4(45.63,3.38) 45.63,8.62 43.48,10.77 R5.1
BSU: length 4.8
  TOP w0.4: 12.5,37.01 12.27,37.24 11.3,37.24 11.23,37.3
  TOP w0.5: IC2.22 11.96,37.26 11.98,37.24 12.21,37.01 v1(12.59,37.01)
  BOTTOM w1: 13.73,36.31 C15.2 13.89,36.69 13.76,36.83 12.76,36.83 v1(12.59,37.01)
BSV: length 5.9
  TOP w0.4: 11.99,30.86 12.55,30.86 12.68,30.99 12.68,31.35 ; 11.99,30.86 IC2.25 ; 11.99,30.86 12.38,31.25 v1(12.45,31.25)
  BOTTOM w0.4: C14.2 13.64,31.64 11.9,31.64
  BOTTOM w1: C14.2 13.68,31.47 13.55,31.34 13.18,31.34 13.1,31.25 v1(12.45,31.25)
BSW: length 13.2
  TOP w0.5: 11.96,23.46 12.45,23.94 12.93,23.94 ; 11.96,23.46 IC2.29 ; 11.96,23.46 12.86,23.46 ; 13.57,23.77 13.26,23.46 12.86,23.46 ; 13.57,23.77 13.57,23.87 ; 13.57,23.77 13.4,23.94 12.93,23.94 ; 12.93,23.94 13.15,23.73 v1(13.2,23.73) 13.16,23.69 13.09,23.69 12.86,23.46
  BOTTOM w0.4: 14.44,23.73 14.44,23.74 14.14,24.04 12.59,24.04 13.26,23.37 ; 14.52,23.37 14.25,23.1 13.52,23.1 ; 14.52,23.37 13.26,23.37 ; 14.52,23.37 C13.2 ; 13.93,22.87 13.76,22.87 13.52,23.1 ; 13.52,23.1 13.26,23.37
  BOTTOM w0.5: 14.58,23.44 C13.2 14.58,23.59 14.44,23.73 v1(13.2,23.73)
DIAG: length 76.2
  TOP w0.3: 67.18,22.4 67.22,22.44 67.38,22.44 67.62,22.68 ; 67.18,22.4 57.41,22.4 ; 67.18,22.4 67.62,22.4 ; 55.89,22.15 57.66,22.15 ; 55.89,22.15 55.57,22.15 ; 55.89,22.15 55.8,22.06 55.22,22.06 55.11,22.17 55.11,22.65 55.21,22.75 55.52,22.75 55.87,22.4 ; 57.66,22.15 67.45,22.15 ; 57.66,22.15 57.41,22.4 ; 67.62,22.68 67.62,22.4 ; 67.62,22.68 67.7,22.76 ; 57.41,22.4 55.87,22.4 ; 67.62,22.4 67.62,22.32 67.45,22.15 ; 67.62,22.4 67.66,22.4 67.75,22.32 ; 67.75,22.32 67.75,22.15 ; 67.75,22.32 67.75,22.68 67.83,22.76 ; 67.75,22.15 67.45,22.15 ; 67.75,22.15 67.9,22.15 ; 67.83,22.76 67.92,22.76 ; 67.83,22.76 67.7,22.76 ; 67.7,22.76 67.97,23.03 R65.2 ; 67.9,22.15 68.05,22.15 68.15,22.24 68.15,22.76 67.92,22.76 ; 67.9,22.15 67.9,22.74 67.92,22.76 ; 55.87,22.4 55.37,22.4 v1(55.35,22.39)
  TOP w0.5: 26.94,25.71 27.57,25.08 27.59,25.1 28,25.1 v1(28.04,25.14) 27.47,25.71 26.94,25.71 ; 26.94,25.71 IC2.4
  BOTTOM w0.3: 28.42,24.76 28.29,24.88 ; 28.42,24.76 28.42,25.32 28.29,25.45 27.86,25.45 27.69,25.27 27.69,25.17 27.7,25.16 27.7,24.98 ; 28.42,24.76 28.55,24.63 ; 28.29,24.88 27.8,24.88 27.7,24.98 ; 28.29,24.88 v1(28.04,25.14) ; 52.78,22.26 54.9,22.26 55.2,21.97 55.35,21.97 ; 52.78,22.26 52.93,22.41 54.76,22.41 ; 52.78,22.26 49.06,18.54 34.63,18.54 28.55,24.63 ; 27.7,24.98 27.7,24.8 27.88,24.63 28.55,24.63 ; 55.35,21.97 55.46,21.97 55.69,22.2 55.69,22.54 55.49,22.74 55.09,22.74 54.76,22.41 ; 55.35,21.97 55.34,21.95 55.28,21.95 ; v1(55.35,22.39) 55.32,22.41 54.76,22.41
DIR: length 28
  TOP w0.3: 59.2,40 59.4,39.8 ; 59.2,40 59.2,40.44 ; 59.2,40 59.02,40.18 59.02,40.4 59,40.41 59,40.7 59.04,40.74 ; 59.4,39.8 59.55,39.65 ; 59.4,39.8 59.4,40.02 ; 59.55,39.65 59.55,39.96 ; 59.55,39.65 61.08,38.13 61.38,38.13 ; 59.55,39.96 59.55,40.37 59.9,40.72 JP3.2 59.93,40.74 59.04,40.74 ; 59.55,39.96 61.38,38.13 ; 59.55,39.96 59.48,40.02 59.4,40.02 ; 71.57,38.13 71.83,38.13 72.3,37.66 72.3,37.4 ; 71.57,38.13 61.38,38.13 ; 71.57,38.13 72.3,37.4 ; 72.3,37.4 72.3,36.13 71.27,35.1 IC4.11 ; 59.04,40.74 JP4.2 ; 59.2,40.44 59.4,40.24 59.4,40.02 ; 59.2,40.44 59.25,40.48
FG: length 16.6
  TOP w0.8: v4(52.03,3.38) 52.03,6.37 D3.1 55.81,10.15 56.74,10.15 ; 56.74,10.15 R7.1 ; 56.74,10.15 52.69,6.1 52.69,4.93 52.59,4.84
FGC: length 26.8
  TOP w0.3: R3.2 74.33,40.57 74.33,40.12 74.63,40.12 76.34,38.4 ; 76.34,38.4 76.34,38.64 ; 76.34,38.4 76.34,31.98 75.31,30.95 70.67,30.95 70.43,31.19 69.25,31.19 IC4.5 ; 76.34,38.64 v1(75.38,39.6) 75.38,39.62 74.35,40.64 ; 76.34,38.64 76.34,39.02 74.95,40.41 74.95,40.89 74.91,40.94 74.91,40.98 74.86,41.03
  BOTTOM w0.3: 75.32,39.6 v1(75.38,39.6)
  BOTTOM w1: 75.32,39.6 74.33,40.59 C1.2 R4.2
FGOUT: length 49.4
  TOP w0.3: 61.75,7.3 61.48,7.03 61.48,6.6 R68.1 ; 61.75,7.3 62.02,7.57 ; 61.75,7.3 61.75,6.69 R68.1 ; RN13.1 64.06,17.9 ; RN13.1 63.87,17.76 ; RN13.1 64.11,17.53 ; 65.94,17.53 65.94,17.52 65.47,17.04 ; 65.94,17.53 70.45,17.53 70.92,18 70.92,19.52 69.24,21.19 IC4.1 ; 65.94,17.53 65.36,17.53 65.32,17.57 65.28,17.53 ; 62.02,7.57 62.49,8.04 62.78,8.04 ; 62.02,7.57 62.02,7.29 ; 65.47,17.04 65.45,17.05 65.45,17.4 65.32,17.53 65.32,16.9 ; 65.47,17.04 65.32,16.9 ; 65.47,17.04 65.47,9.8 65.32,9.65 ; R68.1 61.67,6.51 62.02,6.86 62.02,7.29 ; 63.82,17.82 63.87,17.76 ; 63.87,17.76 64.06,17.96 ; 65.32,16.9 65.32,9.91 ; 62.56,7.82 62.02,7.29 ; 62.56,7.82 62.78,8.04 ; 62.56,7.82 63.49,7.82 63.71,8.04 ; 65.32,9.91 65.32,9.65 ; 65.32,9.91 63.45,8.04 ; 65.32,9.65 63.71,8.04 ; 62.78,8.04 63.45,8.04 ; 63.71,8.04 63.45,8.04
  TOP w1: 64.06,18.62 64.06,17.96 ; 64.11,17.53 65.28,17.53
HU: length 4
  TOP w0.3: 28.67,34.19 28.67,34.31 28.28,34.71 IC2.13
HUM: length 38.9
  TOP w0.3: 58.85,24.84 58.29,24.28 ; 58.85,24.84 59.39,24.84 ; 58.85,24.84 58.85,24.73 ; 58.29,24.28 58.29,24.08 ; 58.29,24.28 58.33,24.28 ; v1(58.8,23.92) 58.72,24 58.61,24 ; v1(58.8,23.92) 58.69,23.92 58.61,24 ; v1(58.8,23.92) 59.26,24.38 ; 58.85,24.38 58.43,24.38 58.33,24.28 ; 58.85,24.38 58.85,24.73 ; 58.85,24.38 58.54,24.07 ; 58.29,24.08 58.37,24 58.47,24 ; 58.29,24.08 58.29,23.88 58.56,23.61 59.02,23.61 59.26,23.85 59.26,24.38 ; 58.47,24 58.54,24.07 ; 58.47,24 58.61,24 ; 58.85,24.73 59.06,24.52 ; 59.39,24.84 59.06,24.52 ; 59.39,24.84 59.72,24.84 ; 58.61,24 58.54,24.07 ; 58.54,24.07 58.33,24.28 ; 63.65,28.6 IC4.28 63.68,28.17 ; 63.65,28.6 63.68,28.58 63.68,28.17 ; 63.65,28.6 63.8,28.6 63.83,28.58 63.83,28.02 ; 59.06,24.52 58.74,24.2 ; 59.26,24.38 59.72,24.84 ; 59.72,24.84 63.25,24.84 64.01,25.61 64.01,27.83 63.83,28.02 ; 63.83,28.02 63.68,28.17
  BOTTOM w0.3: 61.5,14.6 HALL1.2 ; 61.5,14.6 61.3,14.8 61.3,15.22 ; 61.5,14.6 61.26,14.6 61.06,14.8 61.06,15.13 ; C3.2 58.68,22.65 58.68,17.78 58.73,17.73 ; 61.88,14.97 61.55,14.97 61.3,15.22 ; 61.3,15.22 61.06,15.47 ; 61.06,15.47 61.06,15.13 ; 61.06,15.47 60.72,15.47 ; 58.73,17.73 58.09,17.09 58.09,15.69 58.31,15.47 60.72,15.47 ; 58.73,17.73 58.93,17.93 58.93,22.8 ; 61.06,15.13 60.72,15.47 ; 58.71,22.78 58.8,22.87
  BOTTOM w1: 58.8,22.87 v1(58.8,23.92)
HUP: length 24.9
  TOP w0.3: 61.23,24.34 60.93,24.05 60.93,23.89 60.73,23.69 60.4,23.69 60.28,23.81 60.28,24.2 60.29,24.2 60.44,24.34 60.98,24.34 ; 61.23,24.34 63.46,24.34 64.51,25.4 64.51,28.94 64.18,29.27 63.16,29.27 ; 61.23,24.34 60.98,24.34 ; 60.98,24.34 60.64,24.01 v1(60.6,24.01)
  BOTTOM w0.3: 59.66,17.43 59.66,21.17 ; 59.66,17.43 59.51,17.28 ; 59.66,17.43 59.66,16.7 ; 59.66,21.17 59.77,21.17 60.92,22.32 ; 59.66,21.17 59.66,21.42 60.28,22.03 ; C3.1 60.28,22.44 60.28,22.03 ; 59.51,17.28 59.35,17.12 59.35,16.7 ; 59.51,17.28 59.51,16.7 ; 60.28,22.03 60.66,22.42 60.66,22.66 60.71,22.71 ; 59.51,16.54 59.66,16.7 ; 59.51,16.54 59.46,16.5 HALL1.4 59.35,16.5 59.35,16.7 ; 59.51,16.54 59.51,16.7 ; 59.66,16.7 59.51,16.7 ; 59.35,16.7 59.51,16.7
  BOTTOM w1: v1(60.6,24.01) 60.6,22.7
HV: length 42.8
  TOP w0.3: 28.85,35.71 29.32,35.23 29.32,33.36 arc(40.25,20.66) 54.73,29.1
  TOP w0.5: IC2.14 28.85,35.71
HVM: length 21.7
  TOP w0.3: 62.01,27.77 62.01,29.33 62.57,29.89 63.23,29.89 IC4.26 ; 62.01,27.77 61.7,27.46 v1(61.7,27.4) ; 62.01,27.77 62.01,27.24 61.82,27.05 61.57,27.05
  BOTTOM w0.3: 62.26,26.94 62.41,26.79 63.18,26.79 ; 62.26,26.94 62.11,27.09 ; 62.26,26.94 63.03,26.94 63.18,26.79 ; 67.02,24.21 66.8,24.42 ; 67.02,24.21 67.23,23.99 67.23,23.61 HALL2.2 ; 67.02,24.21 67.02,23.68 67.22,23.48 HALL2.2 ; 66.8,24.42 67.14,24.42 67.43,24.13 67.43,23.56 HALL2.2 ; 66.8,24.42 64.27,24.42 63.47,25.22 ; C4.2 63.32,26.65 63.32,25.38 ; C4.2 63.18,26.79 ; C4.2 62.13,26.68 61.42,27.39 ; C4.2 63.16,26.56 63.16,25.53 63.32,25.38 ; 63.47,25.22 63.47,26.57 ; 63.47,25.22 63.32,25.38 ; 62.11,27.09 61.81,27.4 v1(61.7,27.4) ; 62.11,27.09 62.11,27.51 62.03,27.59
HVP: length 15.5
  TOP w0.3: 61.49,28.62 61.39,28.72 61.39,29.42 ; 61.24,29.27 61.39,29.42 ; 61.24,29.27 60.95,28.99 60.95,28.79 61.17,28.58 v1(61.17,28.47) 61.24,28.54 61.24,29.27 ; 61.39,29.42 62.51,30.54 63.23,30.54 IC4.25
  BOTTOM w0.3: 62.07,28.7 63.07,28.7 C4.1 ; 62.07,28.7 62.07,28.47 ; 62.07,28.7 61.38,28.7 61.26,28.82 61.05,28.82 60.81,28.58 60.81,28.49 ; 62.07,28.7 62.08,28.71 ; v1(61.17,28.47) 62.07,28.47 ; 62.07,28.47 62.98,28.47 ; 63.65,28.38 64.92,27.11 ; 64.92,27.11 64.92,25.58 65.12,25.38 HALL2.4 ; 64.92,27.11 65.14,26.89 65.14,25.38
HW: length 43.8
  TOP w0.3: 29.17,36.71 29.54,36.71 29.99,36.26 29.99,36.01 29.93,35.94 ; 29.17,36.71 29.93,35.94 ; 29.17,36.71 IC2.15 ; 29.93,35.94 29.9,33.77 arc(37.57,22.11) 51.26,24.79 arc(52.92,26.86) 54.11,29.24
HWM: length 24.1
  TOP w0.3: 62.08,31.2 61.65,31.2 61.56,31.11 v1(61.45,31.11) ; 62.08,31.2 61.6,30.72 61.32,30.72 61.1,30.94 61.1,30.94 61.1,31.2 61.09,31.21 62.07,31.21 62.08,31.2 ; 62.08,31.2 IC4.24
  BOTTOM w0.3: 63.33,31.31 63.7,31.31 64.03,31.65 ; 63.33,31.31 63.42,31.23 63.94,31.23 64.37,31.65 64.37,31.98 ; 63.33,31.31 C5.2 ; 63.33,31.31 63.21,31.31 ; 62,31.11 v1(61.45,31.11) 61.65,31.31 63.21,31.31 ; 62,31.11 63.01,31.11 63.21,31.31 ; 62,31.11 61.57,30.69 61.26,30.69 61.08,30.87 61.08,31.24 61.16,31.32 ; C5.2 63.54,31.65 64.03,31.65 ; C5.2 63.21,31.31 ; 68.99,33.97 HALL3.2 69.03,33.99 69.03,34.51 68.58,34.95 68.22,34.95 ; 68.99,33.97 68.7,33.97 68.5,34.17 68.5,34.67 ; 68.99,33.97 68.79,34.17 68.79,34.38 68.5,34.67 ; 68.5,34.67 68.22,34.95 ; 68.22,34.95 65.02,34.95 64.37,34.3 64.37,31.98 ; 64.37,31.98 64.03,31.65
HWP: length 19.8
  TOP w0.3: 62.11,31.85 IC4.23 ; 62.11,31.85 61.9,31.85 61.76,31.99 ; 62.11,31.85 61.58,32.39 ; 61.76,31.99 61.22,31.99 61.03,32.18 ; 61.76,31.99 61.5,32.26 v1(61.39,32.26)
  BOTTOM w0.3: 63.51,34.16 63.29,33.95 63.29,33.2 ; 63.51,34.16 63.51,33.41 63.29,33.2 ; 63.51,34.16 63.74,34.39 ; 63.47,33.18 63.33,33.03 62.16,33.03 61.78,32.65 ; 63.47,33.18 63.74,32.92 ; 63.47,33.18 63.45,33.2 ; C5.1 61.92,33.17 61.14,32.4 ; C5.1 63.37,33.17 63.72,33.52 63.72,33.62 63.74,33.64 63.74,34.39 ; C5.1 63.29,33.2 ; 65.06,35.72 63.74,34.39 ; 65.06,35.72 66.63,35.72 HALL3.4 65.22,35.87 65.06,35.72 ; v1(61.39,32.26) 61.78,32.65 ; 61.78,32.65 61.78,32.16 61.64,32.03 61.64,31.99 61.19,31.99 61.02,32.17 61.02,32.23
IDC: length 114.6
  TOP w0.3: 59.7,37.58 59.05,38.22 59.05,38.38 58.88,38.55 58.65,38.55 58.44,38.35 58.44,38.33 ; 59.7,37.58 59.44,37.58 ; 59.7,37.58 67.43,37.58 67.69,37.32 ; v1(58.81,38.19) 58.83,38.19 59.11,37.91 ; 55.97,26.25 55.97,26.26 55.97,26.27 ; 55.97,26.25 55.97,25.99 55.8,25.81 55.27,25.81 ; 55.97,26.25 55.91,26.32 55.27,26.32 ; 59.44,37.58 58.99,37.58 58.78,37.79 ; 59.44,37.58 59.11,37.91 ; 54.93,20.61 58.5,20.61 R24.1 55.15,20.39 54.93,20.61 ; 54.93,20.61 53.86,21.69 53.86,24.4 55.27,25.81 ; 67.69,37.32 67.96,37.05 IC4.14 ; 67.69,37.32 69.64,37.32 69.69,37.27 ; 58.78,37.79 58.98,37.79 59.11,37.91 ; 58.78,37.79 58.47,38.09 ; 55.27,25.81 v1(55.63,26.17) ; 55.27,25.81 55.27,26.32 ; 55.27,26.32 55.31,26.36
  BOTTOM w0.3: 57.81,38.19 57.3,37.69 ; 57.81,38.19 57.39,38.19 57.3,38.11 ; 57.81,38.19 58.7,38.19 ; 57.3,37.69 57.3,27.84 56.01,26.55 ; 57.3,37.69 57.3,38.11 ; 59.18,38.18 59.18,38.35 59.04,38.49 ; 59.04,38.49 58.91,38.62 58.35,38.62 ; 59.04,38.49 58.49,38.49 ; 55.31,25.85 55.31,26.38 55.48,26.55 56.01,26.55 ; 55.31,25.85 56.01,26.55 ; 55.31,25.85 48.62,19.16 36.26,19.16 27.82,27.6 27.82,28.79 23.07,33.54 23.07,40.03 21.53,41.58 18.09,41.58 ; 55.31,25.85 55.83,25.85 56.01,26.02 56.01,26.55 ; 58.4,38.49 58.7,38.19 ; 58.4,38.49 58.49,38.49 ; 58.4,38.49 58.27,38.62 ; 58.4,38.49 57.44,38.49 C25.2 58.27,38.62 ; 58.7,38.19 58.78,38.19 ; 58.35,38.62 58.49,38.49 ; 58.35,38.62 58.27,38.62 ; 58.49,38.49 58.78,38.19 ; RT1.1 16.99,41.4 17.85,41.4 18.02,41.58 ; RT1.1 17.08,41.84 17.83,41.84 18.09,41.58 ; RT1.1 18.02,41.58 ; 18.09,41.58 18.02,41.58 ; 58.78,38.19 v1(58.81,38.19) ; 57.3,38.11 57.3,38.54
IS: length 79.6
  TOP w0.5: 14.97,41.88 15.28,41.58 ; 14.97,41.88 14.87,41.98 14.75,41.98 14.6,42.13 v1(13.75,42.13) 13.5,41.88 ; 14.97,41.88 13.5,41.88 ; 15.28,41.58 15.28,41.46 ; 15.28,41.58 15.25,41.55 14.51,41.55 ; 14.67,26.55 14.28,26.94 ; 14.67,26.55 v1(14.72,26.55) ; 14.67,26.55 10.75,26.55 10.64,26.65 10.93,26.94 14.18,26.94 ; 14.28,26.94 14.18,26.94 ; 14.28,26.94 14.72,26.94 ; IC2.28 14.72,26.16 v1(14.72,26.55) ; v1(14.72,26.55) 14.72,26.94 ; 13.5,41.88 13.16,41.55 ; 13.5,41.88 13.15,41.88 13.09,41.93 ; 13.16,41.55 14.51,41.55 ; 13.16,41.55 12.9,41.29 ; 10.45,41.27 10.47,41.29 12.45,41.29 ; 15.7,41.76 15.72,41.79 15.72,42.13 15.28,42.58 14.75,42.58 ; 13.09,41.93 13.74,42.58 14.75,42.58 ; 13.09,41.93 12.45,41.29 ; 14.18,26.94 13.96,27.16 IC2.27 ; 14.72,26.94 14.97,26.94 15.35,27.32 ; 15.59,26.13 15.71,26.13 ; 15.59,26.13 15.46,26.13 ; 15.59,26.13 15.35,26.36 15.35,27.03 ; 15.35,34.05 15.35,27.32 ; 15.46,26.13 14.81,26.13 ; 15.46,26.13 v1(15.49,26.17) ; 15.35,27.32 15.35,27.11 ; 12.45,41.29 12.9,41.29 ; 14.51,41.55 14.51,41.46 14.94,41.03 ; IC2.20 12.57,40.96 12.9,41.29 ; 14.75,42.58 15.41,41.91
  TOP w1: 15.48,27.09 15.48,27.48 ; 15.48,27.48 15.22,27.22 14.56,27.22 13.89,26.55 ; 15.48,27.48 15.48,28.04 15.35,28.17 ; v1(15.51,26.95) 15.34,26.95 15.22,26.82 14.99,26.82
  BOTTOM w0.5: 13.6,41.73 13.6,41.77 ; 13.6,41.77 14.56,41.77 15.16,42.36 15.16,42.89 ; 13.6,41.77 13.45,41.91 13.45,42.33 13.75,42.62 14.23,42.62 ; 14.23,42.62 v1(13.75,42.13) 14.4,42.13 15.16,42.89 ; 14.23,42.62 15.11,43.5 16.38,43.5 16.54,43.66 ; 15.16,42.89 15.49,43.22 16.66,43.22 RT1.2 16.54,43.66 ; v1(15.51,26.95) 15.47,26.91 15.14,26.91 14.77,26.55 15.12,26.2 15.45,26.2 ; 16.98,43.15 16.98,43.57 16.89,43.66 16.54,43.66 ; 17.08,27.03 16.82,26.77 ; 17.08,29.03 16.79,29.32
  BOTTOM w1: v1(15.49,26.17) 16.35,26.17 17.66,24.85 17.72,24.85 17.72,28.84 17.3,29.26 R26.2 17.14,29.23 17.14,28.37 ; v1(15.49,26.17) 15.11,26.55 v1(14.72,26.55) ; v1(15.49,26.17) 15.57,26.24 16.85,26.24 R25.2 17.14,26.53 17.14,28.37 ; 17.14,28.37 17.08,28.37 ; 15.54,26.97 v1(15.51,26.95) ; 15.54,26.97 16.25,26.97 ; 15.54,26.97 16.94,28.37 17.08,28.37 ; 17.08,28.37 17.08,29.03 ; 17.08,28.37 17.08,27.03
LA: length 38.6
  TOP w0.3: 62.13,39.16 62.34,38.95 ; 62.13,39.16 62.04,39.25 62.04,39.79 ; 62.13,39.16 61.46,39.16 ; 62.34,38.95 62.64,38.65 ; 62.34,38.95 62.3,38.91 61.71,38.91 ; 61.46,40 61.88,40 62.04,40.17 ; 61.46,40 61.46,39.79 ; 61.46,40 62.14,40.68 R15.1 ; 62.04,39.79 61.46,39.79 ; 62.04,39.79 62.11,39.79 ; 62.04,39.79 62.04,39.86 ; 62.64,38.65 63.27,38.65 ; 62.64,38.65 62.64,38.68 62.94,38.98 ; 62.64,38.65 61.97,38.65 61.71,38.91 ; 62.04,40.17 62.04,40.47 62.24,40.67 ; 62.04,40.17 62.04,39.86 ; 61.46,39.79 61.46,39.16 ; 62.24,40.67 62.24,40.24 ; 62.24,40.67 R15.1 ; 63.27,38.65 72.34,38.65 73.04,37.95 73.04,36.11 70.74,33.81 69.25,33.81 IC4.9 ; 63.27,38.65 62.94,38.98 ; 62.04,39.86 62.11,39.79 ; 62.11,39.79 62.59,39.31 62.59,39.31 ; 62.11,39.79 62.22,39.79 62.24,39.81 ; 62.24,39.81 62.46,39.59 ; 62.24,39.81 62.24,40.24 ; 62.46,39.59 62.46,39.45 62.59,39.31 ; 62.46,39.59 62.59,39.46 ; 62.46,39.59 62.46,40.02 62.24,40.24 ; 61.71,38.91 61.46,39.16 ; R15.1 62.24,40.68 62.59,40.33 62.59,39.46 ; 62.94,38.98 62.61,39.31 62.59,39.31 ; 62.59,39.31 62.59,39.46
  BOTTOM w0.3: 60.78,40.68 60.9,40.56 ; 61.67,39.17 61.52,39.17 61.31,39.39 61.31,40.24 60.96,40.59 61,40.59 61.7,39.89 61.7,39.51 v1(61.78,39.43)
  BOTTOM w1: 59.12,40.68 60.78,40.68 ; 61,40.59 61,40.13 61.31,39.81 61.7,39.43 v1(61.78,39.43) ; C2.2 60.96,40.59
LAOFS: length 26.9
  TOP w0.3: 65.59,39.72 65.57,39.74 64.89,39.74 ; 65.59,39.72 65.97,39.34 ; 65.59,39.72 65.59,40.34 65.24,40.69 R33.1 64.89,40.44 64.89,39.96 ; 65.59,39.72 65.59,39.49 65.73,39.34 ; 65.97,39.34 72.56,39.34 73.67,38.24 73.67,36.02 70.8,33.15 IC4.8 ; 65.97,39.34 65.73,39.34 ; 64.89,39.96 65.07,39.96 65.14,39.9 ; 64.89,39.96 64.89,39.74 ; 64.89,39.96 64.48,39.96 ; 64.89,39.74 64.48,39.74 ; 64.89,39.74 v1(64.89,39.55) 65,39.55 65.21,39.34 ; 65.21,39.34 64.66,39.34 64.48,39.52 64.48,39.74 ; 65.21,39.34 65.73,39.34 ; 64.48,39.96 64.48,39.74 ; 64.48,39.96 64.67,40.16
  BOTTOM w0.3: 62.98,40.58 63,40.61 ; 64.89,40.59 R34.2
  BOTTOM w1: v1(64.89,39.55) 64.89,40.59 ; 63,40.61 R34.2
LATYPE: length 31.5
  TOP w0.3: 75.76,37.1 75.76,32.29 74.92,31.45 71.09,31.45 70.69,31.85 IC4.6 ; 75.76,37.1 72.47,40.38 72.76,40.38 ; 75.76,37.1 75.76,37.39 72.76,40.38 ; 72.76,40.38 72.46,40.68 R31.2 69.58,40.38
  TOP w0.5: 69.58,40.38 72.47,40.38
  BOTTOM w0.3: 70.4,40.59 70.55,40.43 v1(70.66,40.43)
  BOTTOM w1: C32.2 70.4,40.59 ; R32.2 69.24,40.59
LU: length 60.4
  TOP w0.3: 58.4,35.1 58.18,35.1 56.37,33.29 ; 58.4,35.1 63.13,35.1 ; 58.4,35.1 56.63,33.34 ; 56.37,33.29 56.37,33.07 ; 56.37,33.29 56.23,33.15 56.2,33.15 56.02,32.98 56.02,32.66 56.05,32.66 56.16,32.55 56.41,32.55 56.63,32.76 56.63,32.81 ; 56.37,33.07 56.29,32.99 v1(56.29,32.9) 56.37,32.97 56.37,33.07 ; 56.37,33.07 56.63,33.34 ; 56.63,32.81 56.63,33.34 ; 56.63,32.81 56.64,32.8
  TOP w0.5: 26.58,31.28 26.57,31.28 26.14,31.71 IC2.10 ; 26.58,31.28 26.98,30.88 27.47,30.88 27.6,31.02 ; 26.58,31.28 v1(27.32,31.28)
  BOTTOM w0.3: 27.58,30.95 27.22,30.95 27.16,30.89 ; 27.16,30.89 27.32,30.74 27.73,30.74 ; 27.16,30.89 27.01,31.05 ; 27.71,31.31 27.73,31.28 27.73,30.74 ; v1(27.32,31.28) 27.73,30.74 ; 27.73,30.74 31.76,25.46 arc(44.67,20.37) 55.16,29.43 56.02,32.07 ; 56.02,32.07 56.46,32.51 56.46,32.58 ; 56.02,32.07 56.02,32.72 ; 56.02,32.07 v1(56.29,32.9) 56.2,32.9
LV: length 69.5
  TOP w0.3: 55.96,34.38 57.36,35.78 57.57,35.78 ; 55.96,34.38 v1(55.61,34.02) ; 55.96,34.38 55.39,34.38 55.19,34.17 55.19,33.83 55.36,33.65 55.69,33.65 55.97,33.93 55.97,34.19 57.57,35.78 ; 57.57,35.78 63.15,35.78 ; 26.91,32.48 v1(27.02,32.48) ; 24.91,32.7 IC2.11
  TOP w0.5: 26.69,32.7 26.99,32.4 27.4,32.4 27.4,32.41 27.1,32.7 26.69,32.7 ; 26.69,32.7 24.91,32.7
  BOTTOM w0.3: 55.44,33.63 55.39,33.24 ; 55.44,33.63 55.78,33.63 ; 55.44,33.63 55.49,34.01 ; 55.39,33.24 55.78,33.63 ; 55.39,33.24 55.35,32.94 ; 55.39,33.24 55.35,33.2 ; 28.52,32.4 28.6,32.32 28.49,32.32 28.46,32.35 ; 28.52,32.4 28.46,32.35 ; 28.52,32.4 28.52,32.4 29.15,31.78 ; 28.52,32.4 28.41,32.4 ; 28.52,32.4 28.47,32.45 28.36,32.45 ; 27.58,32.56 27.69,32.45 27.91,32.45 ; 27.58,32.56 27.7,32.67 ; 27.58,32.56 27.09,32.56 v1(27.02,32.48) 27.09,32.4 28.41,32.4 ; 28.46,32.35 28.3,32.18 27.92,32.18 27.89,32.15 26.77,32.15 26.59,32.33 26.59,32.61 26.77,32.78 27.81,32.78 ; 28.46,32.35 28.41,32.4 ; 27.7,32.67 27.81,32.56 ; 27.7,32.67 27.81,32.78 ; 27.81,32.78 28.03,32.78 ; 27.81,32.56 28.03,32.78 ; 27.81,32.56 27.91,32.45 ; 55.78,33.63 55.83,33.68 ; 55.32,33.91 55.35,33.88 55.35,33.2 ; 28.03,32.78 28.73,32.78 29.15,32.37 29.15,31.78 ; 28.03,32.78 28.36,32.45 ; 28.41,32.4 28.36,32.45 ; 55.35,33.2 55.35,32.94 ; 27.91,32.45 28.36,32.45 ; 55.35,32.94 55.21,31.87 arc(43.72,20.74) 30.23,29.34 29.52,31.41 29.15,31.78
LW: length 67.9
  TOP w0.3: 56.61,36.4 56.93,36.4 ; 56.61,36.4 v1(55.59,35.39) 55.53,35.45 55.53,35.7 55.71,35.87 ; 56.61,36.4 56.24,36.4 55.71,35.87 ; 56.93,36.4 55.62,35.09 55.37,35.09 55.2,35.27 55.2,35.64 55.43,35.87 55.71,35.87 ; 56.93,36.4 IC4.16 ; 24.93,33.73 IC2.12 ; 27.64,33.85 v1(27.69,33.9) 27.58,33.9 ; 27.58,33.9 26.87,33.9 26.7,33.73 ; 27.58,33.9 27.41,33.73
  TOP w0.5: 24.93,33.73 27.41,33.73
  BOTTOM w0.3: 27.83,33.87 28.39,33.75 ; 27.83,33.87 28.04,33.66 ; 27.83,33.87 v1(27.69,33.9) ; 27.83,33.87 27.8,33.9 27.79,33.9 ; 28.39,33.75 28.64,33.75 ; 28.39,33.75 28.24,33.75 28.15,33.66 28.04,33.66 ; 27.84,33.95 27.74,33.95 v1(27.69,33.9) ; 27.84,33.95 28.04,34.15 ; 27.84,33.95 27.79,33.9 ; 27.84,33.95 28.44,33.95 ; v1(27.69,33.9) 27.79,33.9 ; 28.44,33.95 28.64,33.75 ; 28.44,33.95 28.24,34.15 28.04,34.15 ; 28.64,33.75 29.41,33.75 29.59,33.57 30.44,30.39 arc(44.29,21.32) 54.81,34.1 54.81,34.2 54.81,34.4 ; 54.81,34.4 55.38,34.97 55.51,34.97 55.59,35.05 55.82,35.05 55.98,35.22 55.98,35.46 55.9,35.55 55.9,35.61 55.82,35.7 55.41,35.7 55.2,35.49 55.2,34.99 ; 54.81,34.4 54.81,34.6 55.2,34.99 ; 28.04,34.15 27.43,34.15 27.3,34.01 27.3,33.83 27.47,33.66 28.04,33.66 ; 55.2,34.99 v1(55.59,35.39)
NETD2_2: length 57.1
  TOP w0.3: 67.04,11.07 66.51,11.07 66.28,10.84 66.28,9.95 66.46,9.77 v1(66.48,9.77) ; 67.04,11.07 R12.1 ; 67.04,11.07 67.04,10.62 ; 67.22,10.62 67.57,10.97 R12.1 ; 67.22,10.62 67.22,10.04 67.08,9.9 ; 67.22,10.62 67.22,10.72 R12.1 ; 67.22,10.62 67.04,10.62 ; 67.08,9.9 66.95,9.76 66.49,9.76 66.47,9.78 66.47,10.44 v1(66.46,10.45) 66.56,10.45 66.73,10.62 67.04,10.62 ; 67.08,9.9 67.04,9.94 67.04,10.62
  TOP w0.5: 52.79,15.43 57.84,15.43 ; 52.79,15.43 51.9,14.54 51.49,14.54 51.34,14.39 51.2,14.25 50.11,14.25 50.05,14.2 ; 52.79,15.43 52.47,15.43 52.25,15.21 51.95,15.21 ; 57.84,15.43 58.35,15.43 ; 57.84,15.43 58.09,15.69 58.55,15.69 ; D4.1 58.55,15.69 ; 58.55,15.69 58.55,15.53 58.45,15.43 58.35,15.43 ; 58.35,15.43 58.47,15.56
  TOP w1.2: 51.2,12.69 51.34,12.83 51.34,14.39 ; 51.2,12.69 50.57,12.06 ; 51.2,12.69 49.94,12.69 ; 51.2,12.69 51.41,12.69 51.55,12.83 ; 50.57,12.06 R6.2 51.55,12.83 ; 50.57,12.06 49.94,12.69 ; 51.55,12.83 51.55,13.5 v1(51.58,13.53) 51.51,13.59 ; 49.09,13.55 v1(50.92,13.55) ; 49.09,13.55 49.94,12.69 ; 49.09,13.55 D2.2 ; 51.36,13.59 51.51,13.59 ; 51.51,13.59 51.58,13.59
  BOTTOM w0.3: 51.99,12.82 51.8,13 51.2,13 51.15,13.05 ; 51.99,12.82 52.17,12.63 ; 51.99,12.82 51.04,12.82 50.49,13.37 50.49,13.71 50.73,13.95 50.98,13.95 50.98,13.94 51.74,13.94 51.92,13.77 51.92,13.18 ; 52.17,12.63 52.19,12.63 52.33,12.78 51.92,13.18 ; 52.17,12.63 51.32,12.63 51.24,12.55 ; 51.92,13.18 51.57,13.54 50.93,13.54 v1(50.92,13.55)
  BOTTOM w0.5: 66.47,9.84 66.48,9.82 v1(66.48,9.77) ; 66.47,9.84 66.47,10.44 v1(66.46,10.45) 66.42,10.49 65.85,10.49 ; 66.47,9.84 65.85,10.45 65.85,10.49 ; 66.47,9.84 66.47,9.78 v1(66.48,9.77) ; 65.28,10.49 66.03,9.74 66.45,9.74 v1(66.48,9.77) ; 65.28,10.49 54.31,10.49 52.17,12.63 ; 65.28,10.49 65.85,10.49
NETD3_2: length 12.7
  TOP w1: 59.9,12.09 59.9,12.51 56.17,12.51 55.2,13.48 D3.2 55.83,11.96 R7.2 59.77,11.96 59.88,11.85
NETHALL1_1: length 57.1
  BOTTOM w0.5: 62.53,19.16 62.78,19.42 62.78,19.94 ; 62.53,19.16 62.53,23.73 ; 62.53,19.16 61.87,18.5 ; 65.4,21.59 65.83,22.03 ; 65.4,21.59 65.4,20.91 R2.1 ; 65.4,21.59 64.97,21.16 ; 65.83,22.03 65.83,21.34 65.77,21.29 65.77,21.07 65.39,20.69 R2.1 ; 65.83,22.03 68.12,22.03 68.69,22.6 68.69,24.83 68.29,25.23 67.51,25.23 HALL2.1 ; 68.86,35.87 68.76,35.97 68.76,36.26 68.29,36.73 67.81,36.73 ; 68.86,35.87 HALL3.1 ; 68.86,35.87 68.66,35.87 67.81,36.73 ; 62.53,23.73 62.78,23.47 62.78,21.44 ; 62.53,23.73 59.33,26.93 59.33,32.15 63.9,36.73 67.81,36.73 ; 63.39,20.84 65.02,20.84 R2.1 ; 63.39,20.84 62.78,21.44 ; 63.39,20.84 62.78,20.84 ; 62.78,19.94 62.78,20.45 ; 62.78,19.94 63.3,20.45 ; 62.78,20.84 62.78,20.45 ; 62.78,20.84 62.78,21.44 ; 62.78,20.45 63.3,20.45 ; 61.87,18.5 61.87,16.6 61.77,16.5 HALL1.1 61.57,18.21 61.87,18.5 ; 63.3,20.45 65.08,20.45
  BOTTOM w1: 65.17,18.67 R2.1
NETHALL1_3: length 65.3
  BOTTOM w0.5: 65.8,30.32 65.73,30.32 65.19,29.78 ; 65.8,30.32 65.8,32.83 ; 65.8,30.32 66.34,29.78 ; 65.8,30.32 65.8,29.78 ; 65.8,29.78 66.34,29.78 ; 65.8,29.78 65.19,29.78 ; 66.34,29.78 67.77,28.34 ; 66.77,33.95 66.69,33.87 66.34,33.87 65.8,33.33 65.8,32.83 ; HALL2.3 65.07,23.55 63.81,23.55 60.07,27.28 60.07,29.13 60.72,29.78 65.19,29.78 ; 59.53,14.06 59.53,14.5 59.43,14.6 HALL1.3 59.35,13.89 59.53,13.71 ; 59.53,14.06 59.8,14.06 60.15,13.71 ; 59.53,14.06 59.53,13.71 ; 65.8,32.83 66.49,33.53 ; 60.15,13.71 59.53,13.71 ; 60.15,13.71 62.77,13.71 65.09,16.03 69.95,16.03 74.13,20.21 74.13,26.66 73.57,27.22 ; 72.45,28.34 73.29,27.5 ; 72.45,28.34 72.29,28.5 ; 72.45,28.34 73.04,28.34 73.27,28.11 73.41,28.11 73.5,28.01 73.5,27.29 73.29,27.5 ; 72.45,28.34 67.77,28.34 ; 73.29,27.5 72.67,27.5 72.28,27.89 R1.2 ; 71.64,28.05 R1A.2 68.06,28.05 67.77,28.34
